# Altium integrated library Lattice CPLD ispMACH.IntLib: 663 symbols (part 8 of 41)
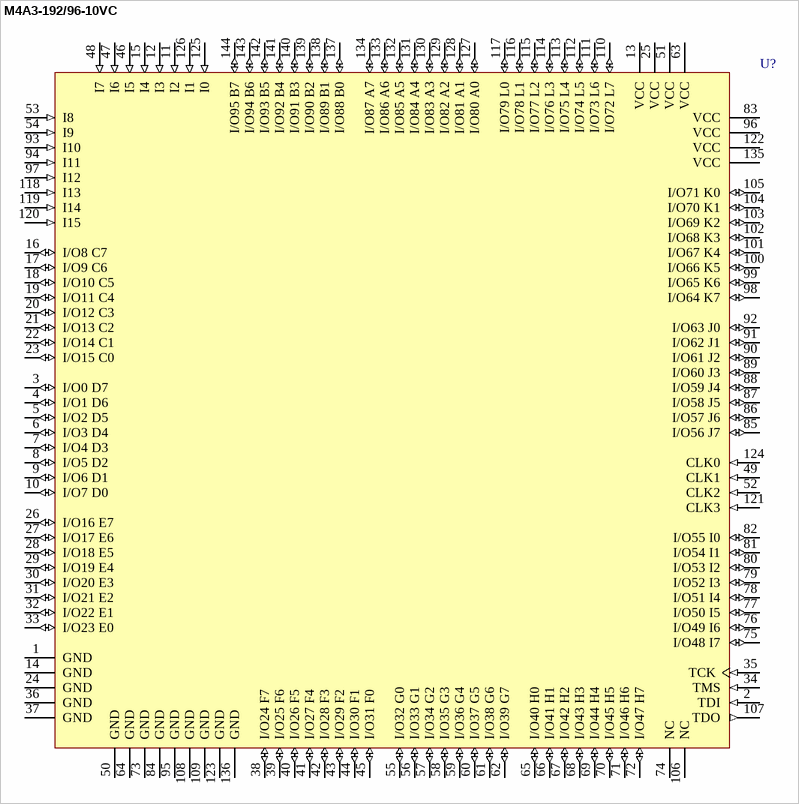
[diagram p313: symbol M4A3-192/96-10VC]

## M4A3-192/96-10VC
designator U?
High-Performance EE CMOS In-System Programmable Logic
footprint TQFP144_N (Thin QFP, 144-Leads, Body 20x20mm, Pitch 0.5mm, IPC Medium Density)
footprint TQFP144_L (Thin QFP, 144-Leads, Body 20x20mm, Pitch 0.5mm, IPC High Density)
footprint TQFP144_M (Thin QFP, 144-Leads, Body 20x20mm, Pitch 0.5mm, IPC Low Density)
3D model M4A3-TQFP144 (144-Pin Thin Quad Flat Pack (TQFP144))
pins: 1 GND (power), 2 TDI (in), 3 I/O0 D7 (io), 4 I/O1 D6 (io), 5 I/O2 D5 (io), 6 I/O3 D4 (io), 7 I/O4 D3 (io), 8 I/O5 D2 (io), 9 I/O6 D1 (io), 10 I/O7 D0 (io), 11 I2 (in), 12 I3 (in), 13 VCC (power), 14 GND (power), 15 I4 (in), 16 I/O8 C7 (io), 17 I/O9 C6 (io), 18 I/O10 C5 (io), 19 I/O11 C4 (io), 20 I/O12 C3 (io), 21 I/O13 C2 (io), 22 I/O14 C1 (io), 23 I/O15 C0 (io), 24 GND (power), 25 VCC (power), 26 I/O16 E7 (io), 27 I/O17 E6 (io), 28 I/O18 E5 (io), 29 I/O19 E4 (io), 30 I/O20 E3 (io), 31 I/O21 E2 (io), 32 I/O22 E1 (io), 33 I/O23 E0 (io), 34 TMS (in), 35 TCK (in), 36 GND (power), 37 GND (power), 38 I/O24 F7 (io), 39 I/O25 F6 (io), 40 I/O26 F5 (io), 41 I/O27 F4 (io), 42 I/O28 F3 (io), 43 I/O29 F2 (io), 44 I/O30 F1 (io), 45 I/O31 F0 (io), 46 I5 (in), 47 I6 (in), 48 I7 (in), 49 CLK1 (in), 50 GND (power), 51 VCC (power), 52 CLK2 (in), 53 I8 (in), 54 I9 (in), 55 I/O32 G0 (io), 56 I/O33 G1 (io), 57 I/O34 G2 (io), 58 I/O35 G3 (io), 59 I/O36 G4 (io), 60 I/O37 G5 (io), 61 I/O38 G6 (io), 62 I/O39 G7 (io), 63 VCC (power), 64 GND (power), 65 I/O40 H0 (io), 66 I/O41 H1 (io), 67 I/O42 H2 (io), 68 I/O43 H3 (io), 69 I/O44 H4 (io), 70 I/O45 H5 (io), 71 I/O46 H6 (io), 72 I/O47 H7 (io), 73 GND (power), 74 NC, 75 I/O48 I7 (io), 76 I/O49 I6 (io), 77 I/O50 I5 (io), 78 I/O51 I4 (io), 79 I/O52 I3 (io), 80 I/O53 I2 (io), 81 I/O54 I1 (io), 82 I/O55 I0 (io), 83 VCC (power), 84 GND (power), 85 I/O56 J7 (io), 86 I/O57 J6 (io), 87 I/O58 J5 (io), 88 I/O59 J4 (io), 89 I/O60 J3 (io), 90 I/O61 J2 (io), 91 I/O62 J1 (io), 92 I/O63 J0 (io), 93 I10 (in), 94 I11 (in), 95 GND (power), 96 VCC (power), 97 I12 (in), 98 I/O64 K7 (io), 99 I/O65 K6 (io), 100 I/O66 K5 (io), 101 I/O67 K4 (io), 102 I/O68 K3 (io), 103 I/O69 K2 (io), 104 I/O70 K1 (io), 105 I/O71 K0 (io), 106 NC, 107 TDO (out), 108 GND (power), 109 GND (power), 110 I/O72 L7 (io), 111 I/O73 L6 (io), 112 I/O74 L5 (io), 113 I/O75 L4 (io), 114 I/O76 L3 (io), 115 I/O77 L2 (io), 116 I/O78 L1 (io), 117 I/O79 L0 (io), 118 I13 (in), 119 I14 (in), 120 I15 (in), 121 CLK3 (in), 122 VCC (power), 123 GND (power), 124 CLK0 (in), 125 I0 (in), 126 I1 (in), 127 I/O80 A0 (io), 128 I/O81 A1 (io), 129 I/O82 A2 (io), 130 I/O83 A3 (io), 131 I/O84 A4 (io), 132 I/O85 A5 (io), 133 I/O86 A6 (io), 134 I/O87 A7 (io), 135 VCC (power), 136 GND (power), 137 I/O88 B0 (io), 138 I/O89 B1 (io), 139 I/O90 B2 (io), 140 I/O91 B3 (io), 141 I/O92 B4 (io), 142 I/O93 B5 (io), 143 I/O94 B6 (io), 144 I/O95 B7 (io)

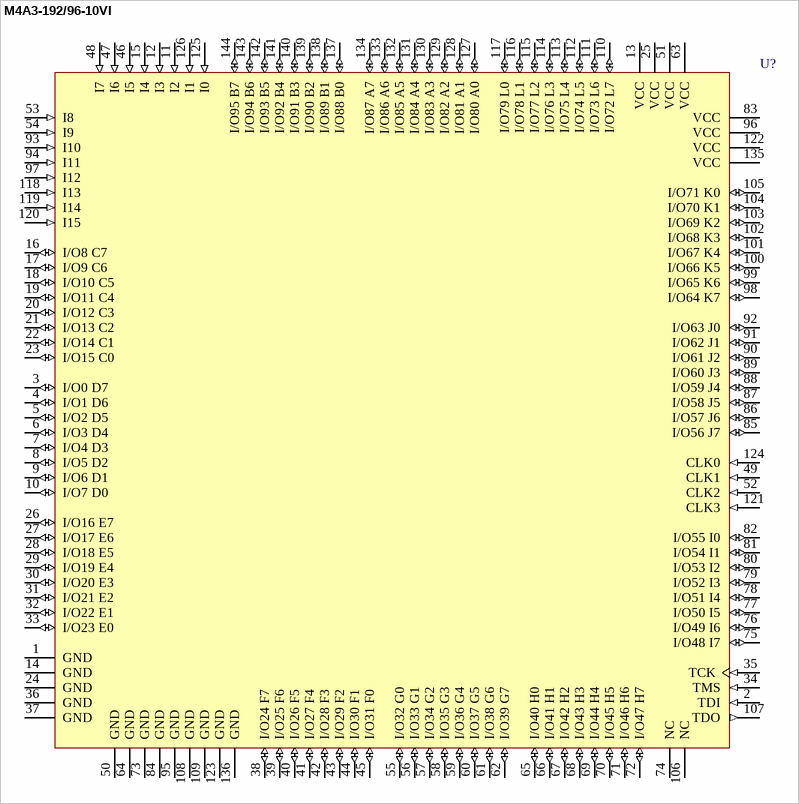
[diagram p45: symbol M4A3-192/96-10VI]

## M4A3-192/96-10VI
designator U?
High-Performance EE CMOS In-System Programmable Logic
footprint TQFP144_N (Thin QFP, 144-Leads, Body 20x20mm, Pitch 0.5mm, IPC Medium Density)
footprint TQFP144_L (Thin QFP, 144-Leads, Body 20x20mm, Pitch 0.5mm, IPC High Density)
footprint TQFP144_M (Thin QFP, 144-Leads, Body 20x20mm, Pitch 0.5mm, IPC Low Density)
3D model M4A3-TQFP144 (144-Pin Thin Quad Flat Pack (TQFP144))
pins: 1 GND (power), 2 TDI (in), 3 I/O0 D7 (io), 4 I/O1 D6 (io), 5 I/O2 D5 (io), 6 I/O3 D4 (io), 7 I/O4 D3 (io), 8 I/O5 D2 (io), 9 I/O6 D1 (io), 10 I/O7 D0 (io), 11 I2 (in), 12 I3 (in), 13 VCC (power), 14 GND (power), 15 I4 (in), 16 I/O8 C7 (io), 17 I/O9 C6 (io), 18 I/O10 C5 (io), 19 I/O11 C4 (io), 20 I/O12 C3 (io), 21 I/O13 C2 (io), 22 I/O14 C1 (io), 23 I/O15 C0 (io), 24 GND (power), 25 VCC (power), 26 I/O16 E7 (io), 27 I/O17 E6 (io), 28 I/O18 E5 (io), 29 I/O19 E4 (io), 30 I/O20 E3 (io), 31 I/O21 E2 (io), 32 I/O22 E1 (io), 33 I/O23 E0 (io), 34 TMS (in), 35 TCK (in), 36 GND (power), 37 GND (power), 38 I/O24 F7 (io), 39 I/O25 F6 (io), 40 I/O26 F5 (io), 41 I/O27 F4 (io), 42 I/O28 F3 (io), 43 I/O29 F2 (io), 44 I/O30 F1 (io), 45 I/O31 F0 (io), 46 I5 (in), 47 I6 (in), 48 I7 (in), 49 CLK1 (in), 50 GND (power), 51 VCC (power), 52 CLK2 (in), 53 I8 (in), 54 I9 (in), 55 I/O32 G0 (io), 56 I/O33 G1 (io), 57 I/O34 G2 (io), 58 I/O35 G3 (io), 59 I/O36 G4 (io), 60 I/O37 G5 (io), 61 I/O38 G6 (io), 62 I/O39 G7 (io), 63 VCC (power), 64 GND (power), 65 I/O40 H0 (io), 66 I/O41 H1 (io), 67 I/O42 H2 (io), 68 I/O43 H3 (io), 69 I/O44 H4 (io), 70 I/O45 H5 (io), 71 I/O46 H6 (io), 72 I/O47 H7 (io), 73 GND (power), 74 NC, 75 I/O48 I7 (io), 76 I/O49 I6 (io), 77 I/O50 I5 (io), 78 I/O51 I4 (io), 79 I/O52 I3 (io), 80 I/O53 I2 (io), 81 I/O54 I1 (io), 82 I/O55 I0 (io), 83 VCC (power), 84 GND (power), 85 I/O56 J7 (io), 86 I/O57 J6 (io), 87 I/O58 J5 (io), 88 I/O59 J4 (io), 89 I/O60 J3 (io), 90 I/O61 J2 (io), 91 I/O62 J1 (io), 92 I/O63 J0 (io), 93 I10 (in), 94 I11 (in), 95 GND (power), 96 VCC (power), 97 I12 (in), 98 I/O64 K7 (io), 99 I/O65 K6 (io), 100 I/O66 K5 (io), 101 I/O67 K4 (io), 102 I/O68 K3 (io), 103 I/O69 K2 (io), 104 I/O70 K1 (io), 105 I/O71 K0 (io), 106 NC, 107 TDO (out), 108 GND (power), 109 GND (power), 110 I/O72 L7 (io), 111 I/O73 L6 (io), 112 I/O74 L5 (io), 113 I/O75 L4 (io), 114 I/O76 L3 (io), 115 I/O77 L2 (io), 116 I/O78 L1 (io), 117 I/O79 L0 (io), 118 I13 (in), 119 I14 (in), 120 I15 (in), 121 CLK3 (in), 122 VCC (power), 123 GND (power), 124 CLK0 (in), 125 I0 (in), 126 I1 (in), 127 I/O80 A0 (io), 128 I/O81 A1 (io), 129 I/O82 A2 (io), 130 I/O83 A3 (io), 131 I/O84 A4 (io), 132 I/O85 A5 (io), 133 I/O86 A6 (io), 134 I/O87 A7 (io), 135 VCC (power), 136 GND (power), 137 I/O88 B0 (io), 138 I/O89 B1 (io), 139 I/O90 B2 (io), 140 I/O91 B3 (io), 141 I/O92 B4 (io), 142 I/O93 B5 (io), 143 I/O94 B6 (io), 144 I/O95 B7 (io)

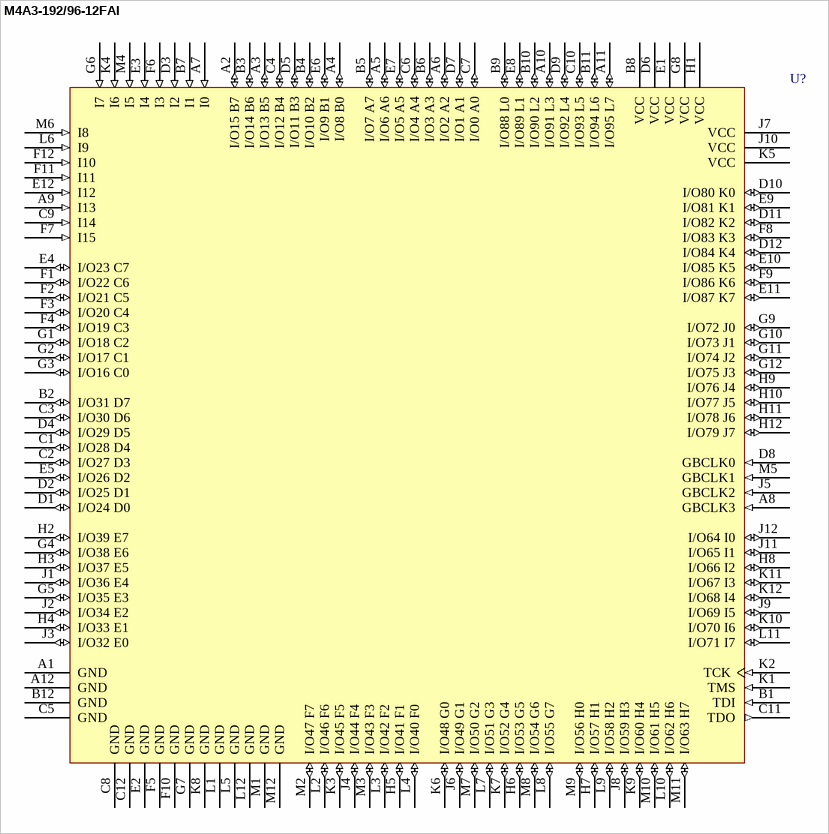
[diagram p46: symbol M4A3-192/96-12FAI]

## M4A3-192/96-12FAI
designator U?
High-Performance EE CMOS In-System Programmable Logic
footprint fpBGA144 (BGA, 144-Leads, Body 13x13mm, Pitch 1mm)
3D model M4A3-fpBGA144 (144-Ball Fine Pitch Ball Grid Array (fpBGA144))
pins: A1 GND (power), A2 I/O15 B7 (io), A3 I/O13 B5 (io), A4 I/O8 B0 (io), A5 I/O6 A6 (io), A6 I/O2 A2 (io), A7 I0 (in), A8 GBCLK3 (in), A9 I13 (in), A10 I/O91 L3 (io), A11 I/O95 L7 (io), A12 GND (power), B1 TDI (in), B2 I/O31 D7 (io), B3 I/O14 B6 (io), B4 I/O10 B2 (io), B5 I/O7 A7 (io), B6 I/O3 A3 (io), B7 I1 (in), B8 VCC (power), B9 I/O88 L0 (io), B10 I/O90 L2 (io), B11 I/O94 L6 (io), B12 GND (power), C1 I/O28 D4 (io), C2 I/O27 D3 (io), C3 I/O30 D6 (io), C4 I/O12 B4 (io), C5 GND (power), C6 I/O4 A4 (io), C7 I/O0 A0 (io), C8 GND (power), C9 I14 (in), C10 I/O93 L5 (io), C11 TDO (out), C12 GND (power), D1 I/O24 D0 (io), D2 I/O25 D1 (io), D3 I2 (in), D4 I/O29 D5 (io), D5 I/O11 B3 (io), D6 VCC (power), D7 I/O1 A1 (io), D8 GBCLK0 (in), D9 I/O92 L4 (io), D10 I/O80 K0 (io), D11 I/O82 K2 (io), D12 I/O84 K4 (io), E1 VCC (power), E2 GND (power), E3 I4 (in), E4 I/O23 C7 (io), E5 I/O26 D2 (io), E6 I/O9 B1 (io), E7 I/O5 A5 (io), E8 I/O89 L1 (io), E9 I/O81 K1 (io), E10 I/O85 K5 (io), E11 I/O87 K7 (io), E12 I12 (in), F1 I/O22 C6 (io), F2 I/O21 C5 (io), F3 I/O20 C4 (io), F4 I/O19 C3 (io), F5 GND (power), F6 I3 (in), F7 I15 (in), F8 I/O83 K3 (io), F9 I/O86 K6 (io), F10 GND (power), F11 I11 (in), F12 I10 (in), G1 I/O18 C2 (io), G2 I/O17 C1 (io), G3 I/O16 C0 (io), G4 I/O38 E6 (io), G5 I/O35 E3 (io), G6 I7 (in), G7 GND (power), G8 VCC (power), G9 I/O72 J0 (io), G10 I/O73 J1 (io), G11 I/O74 J2 (io), G12 I/O75 J3 (io), H1 VCC (power), H2 I/O39 E7 (io), H3 I/O37 E5 (io), H4 I/O33 E1 (io), H5 I/O41 F1 (io), H6 I/O53 G5 (io), H7 I/O57 H1 (io), H8 I/O66 I2 (io), H9 I/O76 J4 (io), H10 I/O77 J5 (io), H11 I/O78 J6 (io), H12 I/O79 J7 (io), J1 I/O36 E4 (io), J2 I/O34 E2 (io), J3 I/O32 E0 (io), J4 I/O44 F4 (io), J5 GBCLK2 (in), J6 I/O49 G1 (io), J7 VCC (power), J8 I/O59 H3 (io), J9 I/O69 I5 (io), J10 VCC (power), J11 I/O65 I1 (io), J12 I/O64 I0 (io), K1 TMS (in), K2 TCK (in), K3 I/O45 F5 (io), K4 I6 (in), K5 VCC (power), K6 I/O48 G0 (io), K7 I/O52 G4 (io), K8 GND (power), K9 I/O60 H4 (io), K10 I/O70 I6 (io), K11 I/O67 I3 (io), K12 I/O68 I4 (io), L1 GND (power), L2 I/O46 F6 (io), L3 I/O42 F2 (io), L4 I/O40 F0 (io), L5 GND (power), L6 I9 (in), L7 I/O51 G3 (io), L8 I/O55 G7 (io), L9 I/O58 H2 (io), L10 I/O62 H6 (io), L11 I/O71 I7 (io), L12 GND (power), M1 GND (power), M2 I/O47 F7 (io), M3 I/O43 F3 (io), M4 I5 (in), M5 GBCLK1 (in), M6 I8 (in), M7 I/O50 G2 (io), M8 I/O54 G6 (io), M9 I/O56 H0 (io), M10 I/O61 H5 (io), M11 I/O63 H7 (io), M12 GND (power)

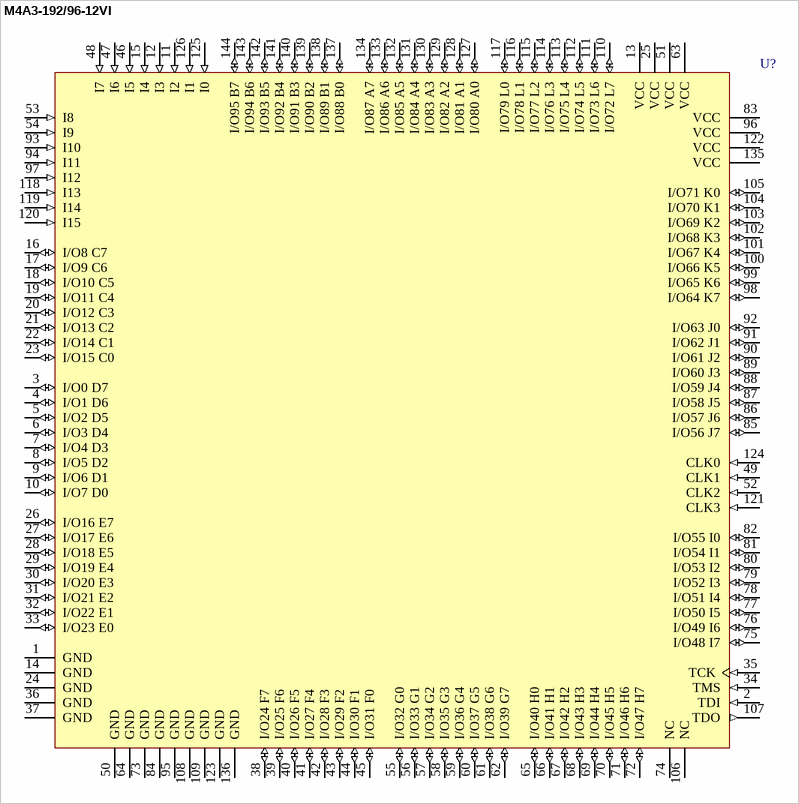
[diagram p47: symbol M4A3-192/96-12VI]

## M4A3-192/96-12VI
designator U?
High-Performance EE CMOS In-System Programmable Logic
footprint TQFP144_N (Thin QFP, 144-Leads, Body 20x20mm, Pitch 0.5mm, IPC Medium Density)
footprint TQFP144_L (Thin QFP, 144-Leads, Body 20x20mm, Pitch 0.5mm, IPC High Density)
footprint TQFP144_M (Thin QFP, 144-Leads, Body 20x20mm, Pitch 0.5mm, IPC Low Density)
3D model M4A3-TQFP144 (144-Pin Thin Quad Flat Pack (TQFP144))
pins: 1 GND (power), 2 TDI (in), 3 I/O0 D7 (io), 4 I/O1 D6 (io), 5 I/O2 D5 (io), 6 I/O3 D4 (io), 7 I/O4 D3 (io), 8 I/O5 D2 (io), 9 I/O6 D1 (io), 10 I/O7 D0 (io), 11 I2 (in), 12 I3 (in), 13 VCC (power), 14 GND (power), 15 I4 (in), 16 I/O8 C7 (io), 17 I/O9 C6 (io), 18 I/O10 C5 (io), 19 I/O11 C4 (io), 20 I/O12 C3 (io), 21 I/O13 C2 (io), 22 I/O14 C1 (io), 23 I/O15 C0 (io), 24 GND (power), 25 VCC (power), 26 I/O16 E7 (io), 27 I/O17 E6 (io), 28 I/O18 E5 (io), 29 I/O19 E4 (io), 30 I/O20 E3 (io), 31 I/O21 E2 (io), 32 I/O22 E1 (io), 33 I/O23 E0 (io), 34 TMS (in), 35 TCK (in), 36 GND (power), 37 GND (power), 38 I/O24 F7 (io), 39 I/O25 F6 (io), 40 I/O26 F5 (io), 41 I/O27 F4 (io), 42 I/O28 F3 (io), 43 I/O29 F2 (io), 44 I/O30 F1 (io), 45 I/O31 F0 (io), 46 I5 (in), 47 I6 (in), 48 I7 (in), 49 CLK1 (in), 50 GND (power), 51 VCC (power), 52 CLK2 (in), 53 I8 (in), 54 I9 (in), 55 I/O32 G0 (io), 56 I/O33 G1 (io), 57 I/O34 G2 (io), 58 I/O35 G3 (io), 59 I/O36 G4 (io), 60 I/O37 G5 (io), 61 I/O38 G6 (io), 62 I/O39 G7 (io), 63 VCC (power), 64 GND (power), 65 I/O40 H0 (io), 66 I/O41 H1 (io), 67 I/O42 H2 (io), 68 I/O43 H3 (io), 69 I/O44 H4 (io), 70 I/O45 H5 (io), 71 I/O46 H6 (io), 72 I/O47 H7 (io), 73 GND (power), 74 NC, 75 I/O48 I7 (io), 76 I/O49 I6 (io), 77 I/O50 I5 (io), 78 I/O51 I4 (io), 79 I/O52 I3 (io), 80 I/O53 I2 (io), 81 I/O54 I1 (io), 82 I/O55 I0 (io), 83 VCC (power), 84 GND (power), 85 I/O56 J7 (io), 86 I/O57 J6 (io), 87 I/O58 J5 (io), 88 I/O59 J4 (io), 89 I/O60 J3 (io), 90 I/O61 J2 (io), 91 I/O62 J1 (io), 92 I/O63 J0 (io), 93 I10 (in), 94 I11 (in), 95 GND (power), 96 VCC (power), 97 I12 (in), 98 I/O64 K7 (io), 99 I/O65 K6 (io), 100 I/O66 K5 (io), 101 I/O67 K4 (io), 102 I/O68 K3 (io), 103 I/O69 K2 (io), 104 I/O70 K1 (io), 105 I/O71 K0 (io), 106 NC, 107 TDO (out), 108 GND (power), 109 GND (power), 110 I/O72 L7 (io), 111 I/O73 L6 (io), 112 I/O74 L5 (io), 113 I/O75 L4 (io), 114 I/O76 L3 (io), 115 I/O77 L2 (io), 116 I/O78 L1 (io), 117 I/O79 L0 (io), 118 I13 (in), 119 I14 (in), 120 I15 (in), 121 CLK3 (in), 122 VCC (power), 123 GND (power), 124 CLK0 (in), 125 I0 (in), 126 I1 (in), 127 I/O80 A0 (io), 128 I/O81 A1 (io), 129 I/O82 A2 (io), 130 I/O83 A3 (io), 131 I/O84 A4 (io), 132 I/O85 A5 (io), 133 I/O86 A6 (io), 134 I/O87 A7 (io), 135 VCC (power), 136 GND (power), 137 I/O88 B0 (io), 138 I/O89 B1 (io), 139 I/O90 B2 (io), 140 I/O91 B3 (io), 141 I/O92 B4 (io), 142 I/O93 B5 (io), 143 I/O94 B6 (io), 144 I/O95 B7 (io)

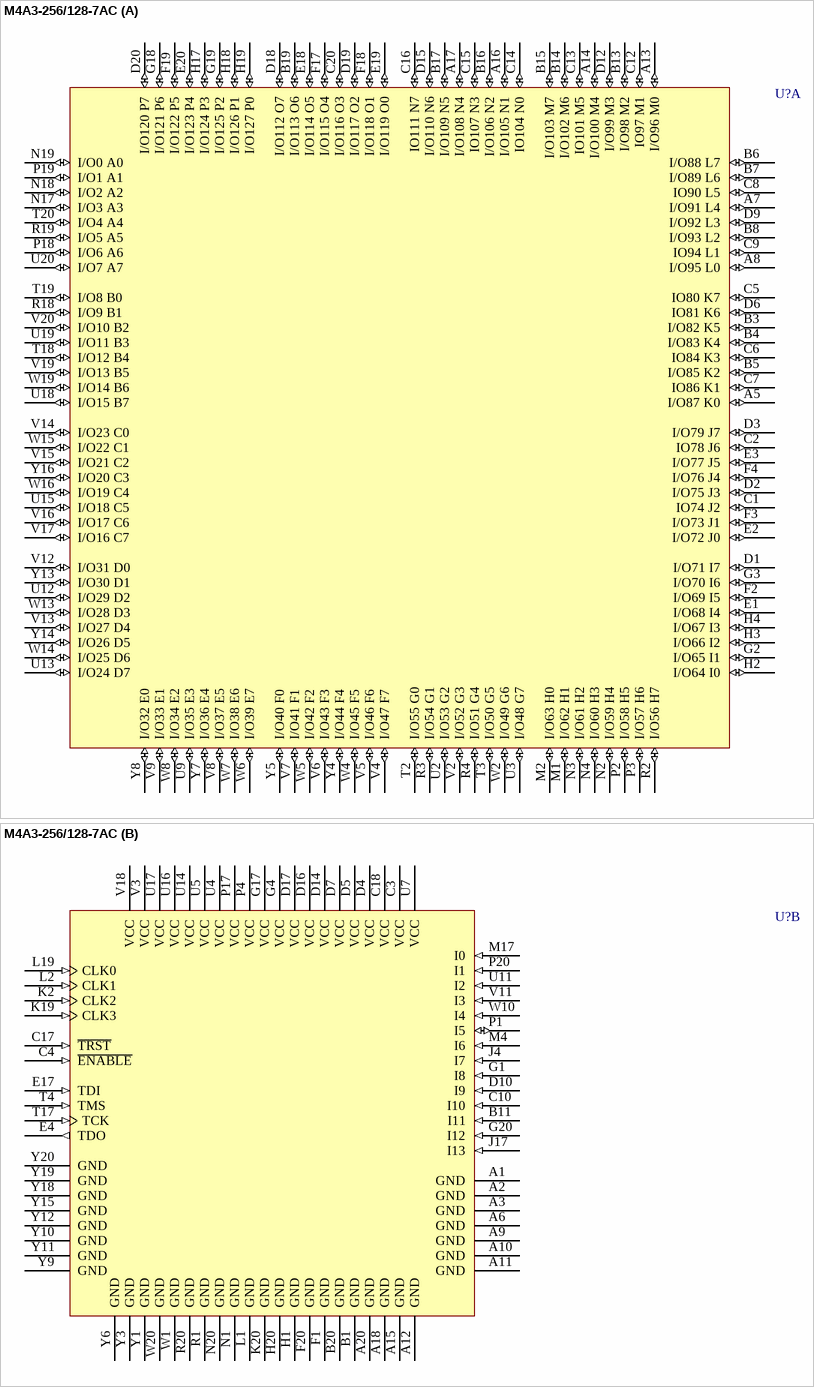
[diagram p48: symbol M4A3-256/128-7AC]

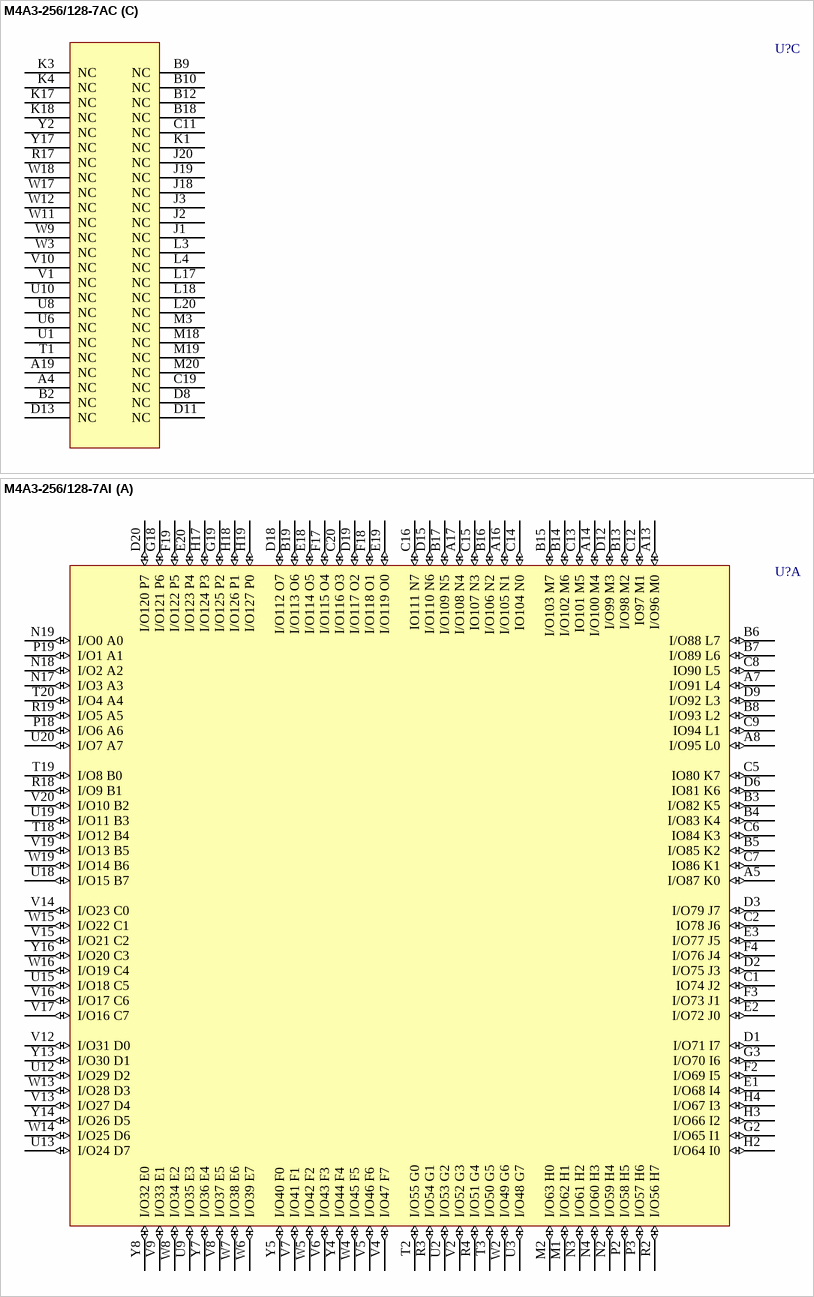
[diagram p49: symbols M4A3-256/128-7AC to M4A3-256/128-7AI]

## M4A3-256/128-7AC
designator U?
High-Performance EE CMOS In-System Programmable Logic
footprint SBGA256 (BGA, 256-Leads, Body 27x27mm, Pitch 1.27mm)
3D model M4A3-SBGA256 (256-Ball Super Ball Grid Array (SBGA256))
part A pins: A5 I/O87 K0 (io), A7 I/O91 L4 (io), A8 I/O95 L0 (io), A13 I/O96 M0 (io), A14 I/O100 M4 (io), A16 I/O105 N1 (io), A17 I/O108 N4 (io), B3 I/O82 K5 (io), B4 I/O83 K4 (io), B5 I/O85 K2 (io), B6 I/O88 L7 (io), B7 I/O89 L6 (io), B8 I/O93 L2 (io), B13 I/O98 M2 (io), B14 I/O102 M6 (io), B15 I/O103 M7 (io), B16 I/O106 N2 (io), B17 I/O109 N5 (io), B19 I/O113 O6 (io), C1 IO74 J2 (io), C2 IO78 J6 (io), C5 IO80 K7 (io), C6 IO84 K3 (io), C7 IO86 K1 (io), C8 IO90 L5 (io), C9 IO94 L1 (io), C12 IO97 M1 (io), C13 IO101 M5 (io), C14 IO104 N0 (io), C15 IO107 N3 (io), C16 IO111 N7 (io), C20 I/O116 O3 (io), D1 I/O71 I7 (io), D2 I/O75 J3 (io), D3 I/O79 J7 (io), D6 IO81 K6 (io), D9 I/O92 L3 (io), D12 I/O99 M3 (io), D15 I/O110 N6 (io), D18 I/O112 O7 (io), D19 I/O117 O2 (io), D20 I/O120 P7 (io), E1 I/O68 I4 (io), E2 I/O72 J0 (io), E3 I/O77 J5 (io), E18 I/O114 O5 (io), E19 I/O119 O0 (io), E20 I/O123 P4 (io), F2 I/O69 I5 (io), F3 I/O73 J1 (io), F4 I/O76 J4 (io), F17 I/O115 O4 (io), F18 I/O118 O1 (io), F19 I/O122 P5 (io), G2 I/O65 I1 (io), G3 I/O70 I6 (io), G18 I/O121 P6 (io), G19 I/O125 P2 (io), H2 I/O64 I0 (io), H3 I/O66 I2 (io), H4 I/O67 I3 (io), H17 I/O124 P3 (io), H18 I/O126 P1 (io), H19 I/O127 P0 (io), M1 I/O62 H1 (io), M2 I/O63 H0 (io), N2 I/O59 H4 (io), N3 I/O61 H2 (io), N4 I/O60 H3 (io), N17 I/O3 A3 (io), N18 I/O2 A2 (io), N19 I/O0 A0 (io), P2 I/O58 H5 (io), P3 I/O57 H6 (io), P18 I/O6 A6 (io), P19 I/O1 A1 (io), R2 I/O56 H7 (io), R3 I/O54 G1 (io), R4 I/O51 G4 (io), R18 I/O9 B1 (io), R19 I/O5 A5 (io), T2 I/O55 G0 (io), T3 I/O50 G5 (io), T18 I/O12 B4 (io), T19 I/O8 B0 (io), T20 I/O4 A4 (io), U2 I/O53 G2 (io), U3 I/O48 G7 (io), U9 I/O35 E3 (io), U12 I/O29 D2 (io), U13 I/O24 D7 (io), U15 I/O18 C5 (io), U18 I/O15 B7 (io), U19 I/O11 B3 (io), U20 I/O7 A7 (io), V2 I/O52 G3 (io), V4 I/O47 F7 (io), V5 I/O46 F6 (io), V6 I/O43 F3 (io), V7 I/O41 F1 (io), V8 I/O37 E5 (io), V9 I/O33 E1 (io), V12 I/O31 D0 (io), V13 I/O27 D4 (io), V14 I/O23 C0 (io), V15 I/O21 C2 (io), V16 I/O17 C6 (io), V17 I/O16 C7 (io), V19 I/O13 B5 (io), V20 I/O10 B2 (io), W2 I/O49 G6 (io), W4 I/O45 F5 (io), W5 I/O42 F2 (io), W6 I/O39 E7 (io), W7 I/O38 E6 (io), W8 I/O34 E2 (io), W13 I/O28 D3 (io), W14 I/O25 D6 (io), W15 I/O22 C1 (io), W16 I/O19 C4 (io), W19 I/O14 B6 (io), Y4 I/O44 F4 (io), Y5 I/O40 F0 (io), Y7 I/O36 E4 (io), Y8 I/O32 E0 (io), Y13 I/O30 D1 (io), Y14 I/O26 D5 (io), Y16 I/O20 C3 (io)
part B pins: A1 GND (power), A2 GND (power), A3 GND (power), A6 GND (power), A9 GND (power), A10 GND (power), A11 GND (power), A12 GND (power), A15 GND (power), A18 GND (power), A20 GND (power), B1 GND (power), B11 I11 (in), B20 GND (power), C3 VCC (power), C4 ~{ENABLE} (in), C10 I10 (in), C17 ~{TRST} (in), C18 VCC (power), D4 VCC (power), D5 VCC (power), D7 VCC (power), D10 I9 (in), D14 VCC (power), D16 VCC (power), D17 VCC (power), E4 TDO (out), E17 TDI (in), F1 GND (power), F20 GND (power), G1 I8 (in), G4 VCC (power), G17 VCC (power), G20 I12 (in), H1 GND (power), H20 GND (power), J4 I7 (in), J17 I13 (in), K2 CLK2 (in), K19 CLK3 (in), K20 GND (power), L1 GND (power), L2 CLK1 (in), L19 CLK0 (in), M4 I6 (in), M17 I0 (in), N1 GND (power), N20 GND (power), P1 I5 (io), P4 VCC (power), P17 VCC (power), P20 I1 (in), R1 GND (power), R20 GND (power), T4 TMS (in), T17 TCK (in), U4 VCC (power), U5 VCC (power), U7 VCC (power), U11 I2 (in), U14 VCC (power), U16 VCC (power), U17 VCC (power), V3 VCC (power), V11 I3 (in), V18 VCC (power), W1 GND (power), W10 I4 (in), W20 GND (power), Y1 GND (power), Y3 GND (power), Y6 GND (power), Y9 GND (power), Y10 GND (power), Y11 GND (power), Y12 GND (power), Y15 GND (power), Y18 GND (power), Y19 GND (power), Y20 GND (power)
part C pins: A4 NC, A19 NC, B2 NC, B9 NC, B10 NC, B12 NC, B18 NC, C11 NC, C19 NC, D8 NC, D11 NC, D13 NC, J1 NC, J2 NC, J3 NC, J18 NC, J19 NC, J20 NC, K1 NC, K3 NC, K4 NC, K17 NC, K18 NC, L3 NC, L4 NC, L17 NC, L18 NC, L20 NC, M3 NC, M18 NC, M19 NC, M20 NC, R17 NC, T1 NC, U1 NC, U6 NC, U8 NC, U10 NC, V1 NC, V10 NC, W3 NC, W9 NC, W11 NC, W12 NC, W17 NC, W18 NC, Y2 NC, Y17 NC

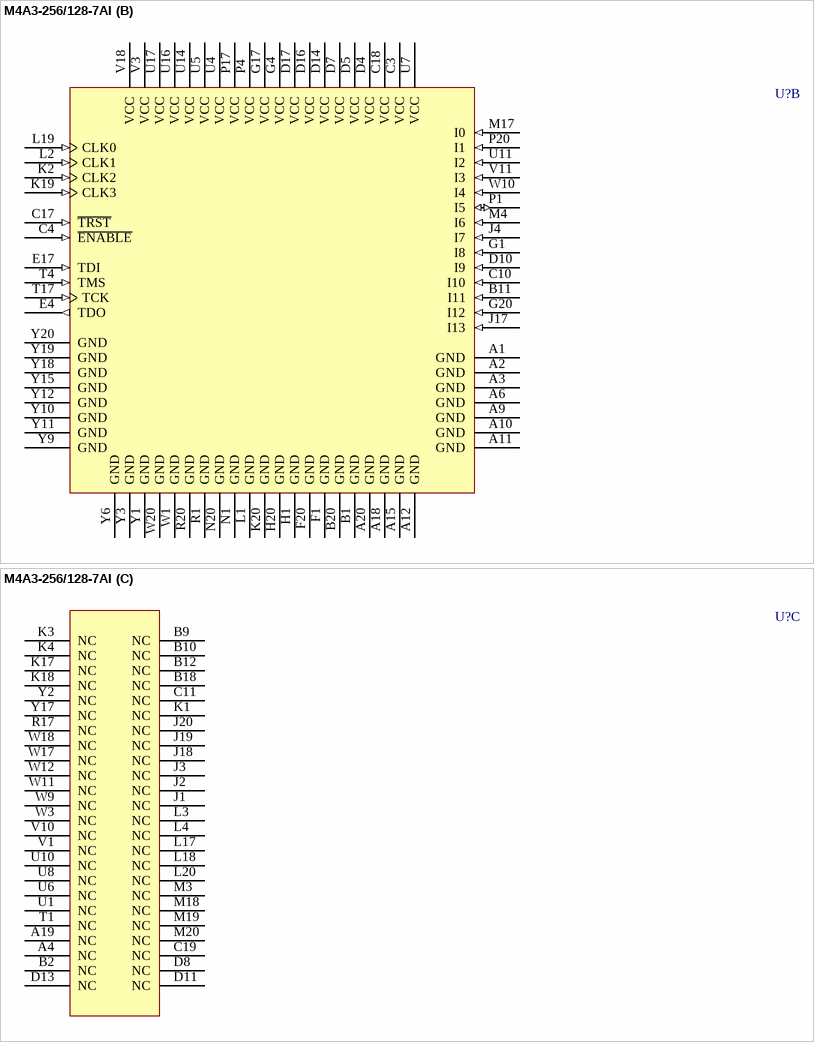
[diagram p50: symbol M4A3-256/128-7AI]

## M4A3-256/128-7AI
designator U?
High-Performance EE CMOS In-System Programmable Logic
footprint SBGA256 (BGA, 256-Leads, Body 27x27mm, Pitch 1.27mm)
3D model M4A3-SBGA256 (256-Ball Super Ball Grid Array (SBGA256))
part A pins: A5 I/O87 K0 (io), A7 I/O91 L4 (io), A8 I/O95 L0 (io), A13 I/O96 M0 (io), A14 I/O100 M4 (io), A16 I/O105 N1 (io), A17 I/O108 N4 (io), B3 I/O82 K5 (io), B4 I/O83 K4 (io), B5 I/O85 K2 (io), B6 I/O88 L7 (io), B7 I/O89 L6 (io), B8 I/O93 L2 (io), B13 I/O98 M2 (io), B14 I/O102 M6 (io), B15 I/O103 M7 (io), B16 I/O106 N2 (io), B17 I/O109 N5 (io), B19 I/O113 O6 (io), C1 IO74 J2 (io), C2 IO78 J6 (io), C5 IO80 K7 (io), C6 IO84 K3 (io), C7 IO86 K1 (io), C8 IO90 L5 (io), C9 IO94 L1 (io), C12 IO97 M1 (io), C13 IO101 M5 (io), C14 IO104 N0 (io), C15 IO107 N3 (io), C16 IO111 N7 (io), C20 I/O116 O3 (io), D1 I/O71 I7 (io), D2 I/O75 J3 (io), D3 I/O79 J7 (io), D6 IO81 K6 (io), D9 I/O92 L3 (io), D12 I/O99 M3 (io), D15 I/O110 N6 (io), D18 I/O112 O7 (io), D19 I/O117 O2 (io), D20 I/O120 P7 (io), E1 I/O68 I4 (io), E2 I/O72 J0 (io), E3 I/O77 J5 (io), E18 I/O114 O5 (io), E19 I/O119 O0 (io), E20 I/O123 P4 (io), F2 I/O69 I5 (io), F3 I/O73 J1 (io), F4 I/O76 J4 (io), F17 I/O115 O4 (io), F18 I/O118 O1 (io), F19 I/O122 P5 (io), G2 I/O65 I1 (io), G3 I/O70 I6 (io), G18 I/O121 P6 (io), G19 I/O125 P2 (io), H2 I/O64 I0 (io), H3 I/O66 I2 (io), H4 I/O67 I3 (io), H17 I/O124 P3 (io), H18 I/O126 P1 (io), H19 I/O127 P0 (io), M1 I/O62 H1 (io), M2 I/O63 H0 (io), N2 I/O59 H4 (io), N3 I/O61 H2 (io), N4 I/O60 H3 (io), N17 I/O3 A3 (io), N18 I/O2 A2 (io), N19 I/O0 A0 (io), P2 I/O58 H5 (io), P3 I/O57 H6 (io), P18 I/O6 A6 (io), P19 I/O1 A1 (io), R2 I/O56 H7 (io), R3 I/O54 G1 (io), R4 I/O51 G4 (io), R18 I/O9 B1 (io), R19 I/O5 A5 (io), T2 I/O55 G0 (io), T3 I/O50 G5 (io), T18 I/O12 B4 (io), T19 I/O8 B0 (io), T20 I/O4 A4 (io), U2 I/O53 G2 (io), U3 I/O48 G7 (io), U9 I/O35 E3 (io), U12 I/O29 D2 (io), U13 I/O24 D7 (io), U15 I/O18 C5 (io), U18 I/O15 B7 (io), U19 I/O11 B3 (io), U20 I/O7 A7 (io), V2 I/O52 G3 (io), V4 I/O47 F7 (io), V5 I/O46 F6 (io), V6 I/O43 F3 (io), V7 I/O41 F1 (io), V8 I/O37 E5 (io), V9 I/O33 E1 (io), V12 I/O31 D0 (io), V13 I/O27 D4 (io), V14 I/O23 C0 (io), V15 I/O21 C2 (io), V16 I/O17 C6 (io), V17 I/O16 C7 (io), V19 I/O13 B5 (io), V20 I/O10 B2 (io), W2 I/O49 G6 (io), W4 I/O45 F5 (io), W5 I/O42 F2 (io), W6 I/O39 E7 (io), W7 I/O38 E6 (io), W8 I/O34 E2 (io), W13 I/O28 D3 (io), W14 I/O25 D6 (io), W15 I/O22 C1 (io), W16 I/O19 C4 (io), W19 I/O14 B6 (io), Y4 I/O44 F4 (io), Y5 I/O40 F0 (io), Y7 I/O36 E4 (io), Y8 I/O32 E0 (io), Y13 I/O30 D1 (io), Y14 I/O26 D5 (io), Y16 I/O20 C3 (io)
part B pins: A1 GND (power), A2 GND (power), A3 GND (power), A6 GND (power), A9 GND (power), A10 GND (power), A11 GND (power), A12 GND (power), A15 GND (power), A18 GND (power), A20 GND (power), B1 GND (power), B11 I11 (in), B20 GND (power), C3 VCC (power), C4 ~{ENABLE} (in), C10 I10 (in), C17 ~{TRST} (in), C18 VCC (power), D4 VCC (power), D5 VCC (power), D7 VCC (power), D10 I9 (in), D14 VCC (power), D16 VCC (power), D17 VCC (power), E4 TDO (out), E17 TDI (in), F1 GND (power), F20 GND (power), G1 I8 (in), G4 VCC (power), G17 VCC (power), G20 I12 (in), H1 GND (power), H20 GND (power), J4 I7 (in), J17 I13 (in), K2 CLK2 (in), K19 CLK3 (in), K20 GND (power), L1 GND (power), L2 CLK1 (in), L19 CLK0 (in), M4 I6 (in), M17 I0 (in), N1 GND (power), N20 GND (power), P1 I5 (io), P4 VCC (power), P17 VCC (power), P20 I1 (in), R1 GND (power), R20 GND (power), T4 TMS (in), T17 TCK (in), U4 VCC (power), U5 VCC (power), U7 VCC (power), U11 I2 (in), U14 VCC (power), U16 VCC (power), U17 VCC (power), V3 VCC (power), V11 I3 (in), V18 VCC (power), W1 GND (power), W10 I4 (in), W20 GND (power), Y1 GND (power), Y3 GND (power), Y6 GND (power), Y9 GND (power), Y10 GND (power), Y11 GND (power), Y12 GND (power), Y15 GND (power), Y18 GND (power), Y19 GND (power), Y20 GND (power)
part C pins: A4 NC, A19 NC, B2 NC, B9 NC, B10 NC, B12 NC, B18 NC, C11 NC, C19 NC, D8 NC, D11 NC, D13 NC, J1 NC, J2 NC, J3 NC, J18 NC, J19 NC, J20 NC, K1 NC, K3 NC, K4 NC, K17 NC, K18 NC, L3 NC, L4 NC, L17 NC, L18 NC, L20 NC, M3 NC, M18 NC, M19 NC, M20 NC, R17 NC, T1 NC, U1 NC, U6 NC, U8 NC, U10 NC, V1 NC, V10 NC, W3 NC, W9 NC, W11 NC, W12 NC, W17 NC, W18 NC, Y2 NC, Y17 NC

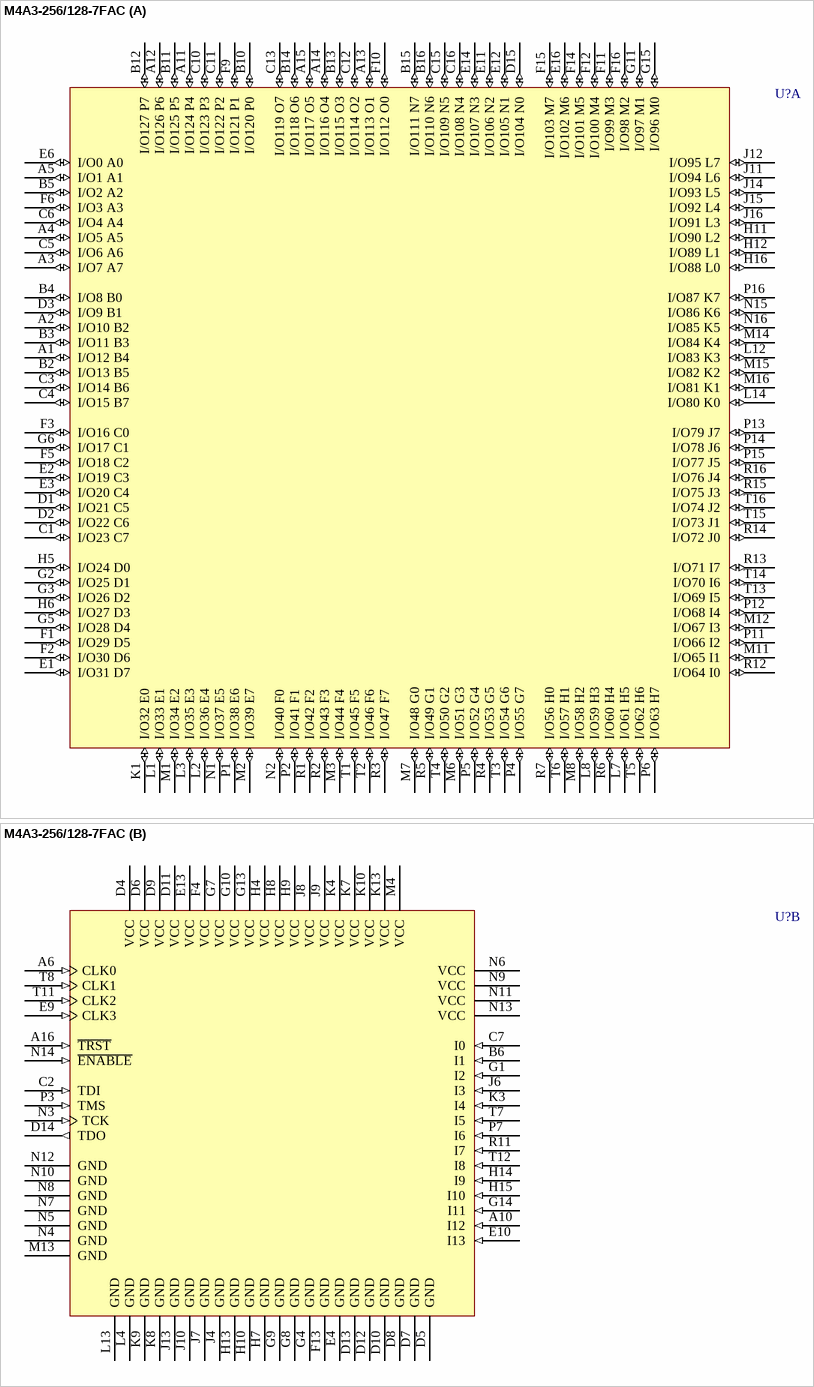
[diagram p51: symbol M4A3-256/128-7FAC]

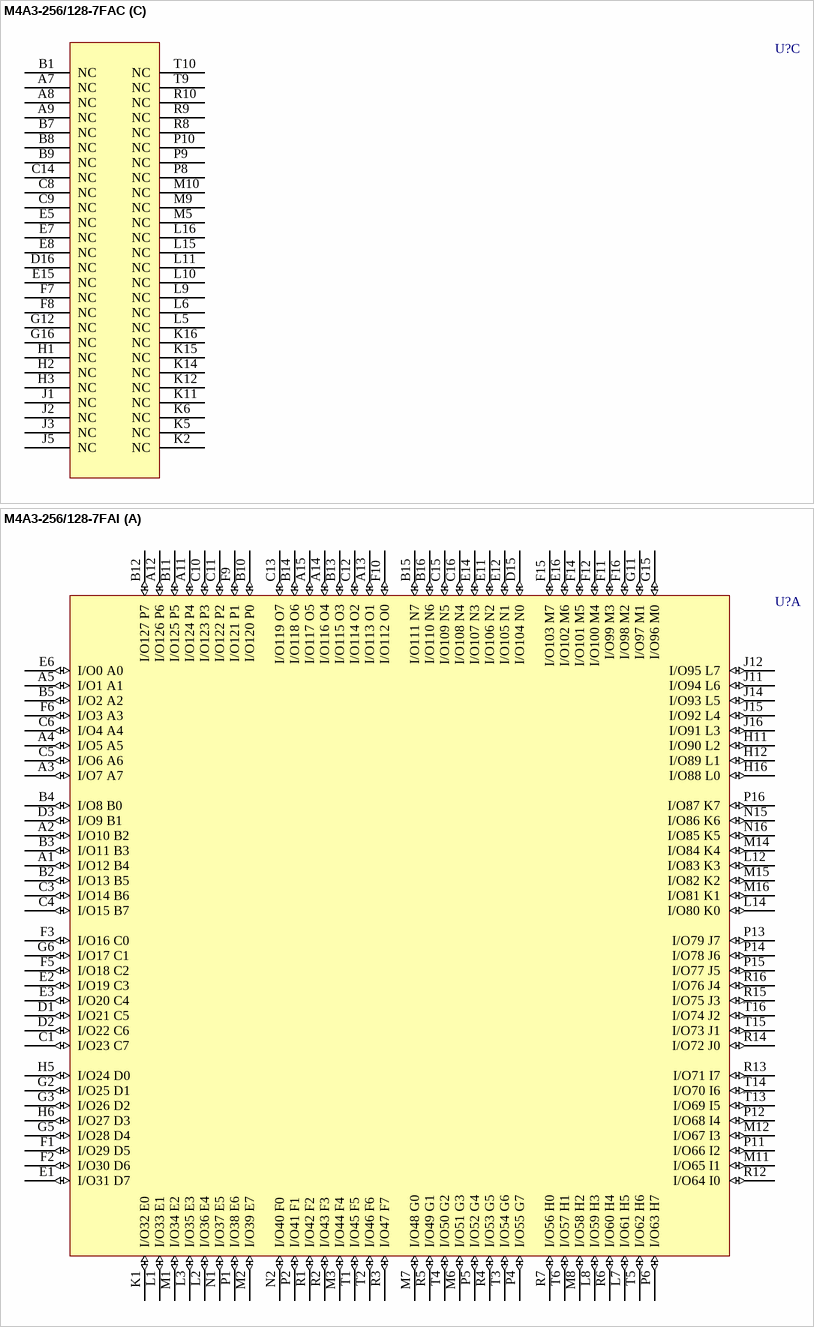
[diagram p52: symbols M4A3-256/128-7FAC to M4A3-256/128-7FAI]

## M4A3-256/128-7FAC
designator U?
High-Performance EE CMOS In-System Programmable Logic
footprint fpBGA256 (BGA, 256-Leads, Body 17x17mm, Pitch 1mm)
3D model M4A3-fpBGA256 (256-Ball Fine Pitch Ball Grid Array (fpBGA256))
part A pins: A1 I/O12 B4 (io), A2 I/O10 B2 (io), A3 I/O7 A7 (io), A4 I/O5 A5 (io), A5 I/O1 A1 (io), A11 I/O124 P4 (io), A12 I/O126 P6 (io), A13 I/O113 O1 (io), A14 I/O116 O4 (io), A15 I/O117 O5 (io), B2 I/O13 B5 (io), B3 I/O11 B3 (io), B4 I/O8 B0 (io), B5 I/O2 A2 (io), B10 I/O120 P0 (io), B11 I/O125 P5 (io), B12 I/O127 P7 (io), B13 I/O115 O3 (io), B14 I/O118 O6 (io), B15 I/O111 N7 (io), B16 I/O110 N6 (io), C1 I/O23 C7 (io), C3 I/O14 B6 (io), C4 I/O15 B7 (io), C5 I/O6 A6 (io), C6 I/O4 A4 (io), C10 I/O123 P3 (io), C11 I/O122 P2 (io), C12 I/O114 O2 (io), C13 I/O119 O7 (io), C15 I/O109 N5 (io), C16 I/O108 N4 (io), D1 I/O21 C5 (io), D2 I/O22 C6 (io), D3 I/O9 B1 (io), D15 I/O104 N0 (io), E1 I/O31 D7 (io), E2 I/O19 C3 (io), E3 I/O20 C4 (io), E6 I/O0 A0 (io), E11 I/O106 N2 (io), E12 I/O105 N1 (io), E14 I/O107 N3 (io), E16 I/O102 M6 (io), F1 I/O29 D5 (io), F2 I/O30 D6 (io), F3 I/O16 C0 (io), F5 I/O18 C2 (io), F6 I/O3 A3 (io), F9 I/O121 P1 (io), F10 I/O112 O0 (io), F11 I/O99 M3 (io), F12 I/O100 M4 (io), F14 I/O101 M5 (io), F15 I/O103 M7 (io), F16 I/O98 M2 (io), G2 I/O25 D1 (io), G3 I/O26 D2 (io), G5 I/O28 D4 (io), G6 I/O17 C1 (io), G11 I/O97 M1 (io), G15 I/O96 M0 (io), H5 I/O24 D0 (io), H6 I/O27 D3 (io), H11 I/O90 L2 (io), H12 I/O89 L1 (io), H16 I/O88 L0 (io), J11 I/O94 L6 (io), J12 I/O95 L7 (io), J14 I/O93 L5 (io), J15 I/O92 L4 (io), J16 I/O91 L3 (io), K1 I/O32 E0 (io), L1 I/O33 E1 (io), L2 I/O36 E4 (io), L3 I/O35 E3 (io), L7 I/O61 H5 (io), L8 I/O59 H3 (io), L12 I/O83 K3 (io), L14 I/O80 K0 (io), M1 I/O34 E2 (io), M2 I/O39 E7 (io), M3 I/O44 F4 (io), M6 I/O51 G3 (io), M7 I/O48 G0 (io), M8 I/O58 H2 (io), M11 I/O65 I1 (io), M12 I/O67 I3 (io), M14 I/O84 K4 (io), M15 I/O82 K2 (io), M16 I/O81 K1 (io), N1 I/O37 E5 (io), N2 I/O40 F0 (io), N15 I/O86 K6 (io), N16 I/O85 K5 (io), P1 I/O38 E6 (io), P2 I/O41 F1 (io), P4 I/O55 G7 (io), P5 I/O52 G4 (io), P6 I/O63 H7 (io), P11 I/O66 I2 (io), P12 I/O68 I4 (io), P13 I/O79 J7 (io), P14 I/O78 J6 (io), P15 I/O77 J5 (io), P16 I/O87 K7 (io), R1 I/O42 F2 (io), R2 I/O43 F3 (io), R3 I/O47 F7 (io), R4 I/O53 G5 (io), R5 I/O49 G1 (io), R6 I/O60 H4 (io), R7 I/O56 H0 (io), R12 I/O64 I0 (io), R13 I/O71 I7 (io), R14 I/O72 J0 (io), R15 I/O75 J3 (io), R16 I/O76 J4 (io), T1 I/O45 F5 (io), T2 I/O46 F6 (io), T3 I/O54 G6 (io), T4 I/O50 G2 (io), T5 I/O62 H6 (io), T6 I/O57 H1 (io), T13 I/O69 I5 (io), T14 I/O70 I6 (io), T15 I/O73 J1 (io), T16 I/O74 J2 (io)
part B pins: A6 CLK0 (in), A10 I12 (in), A16 ~{TRST} (in), B6 I1 (in), C2 TDI (in), C7 I0 (in), D4 VCC (power), D5 GND (power), D6 VCC (power), D7 GND (power), D8 GND (power), D9 VCC (power), D10 GND (power), D11 VCC (power), D12 GND (power), D13 GND (power), D14 TDO (out), E4 GND (power), E9 CLK3 (in), E10 I13 (in), E13 VCC (power), F4 VCC (power), F13 GND (power), G1 I2 (in), G4 GND (power), G7 VCC (power), G8 GND (power), G9 GND (power), G10 VCC (power), G13 VCC (power), G14 I11 (in), H4 VCC (power), H7 GND (power), H8 VCC (power), H9 VCC (power), H10 GND (power), H13 GND (power), H14 I9 (in), H15 I10 (in), J4 GND (power), J6 I3 (in), J7 GND (power), J8 VCC (power), J9 VCC (power), J10 GND (power), J13 GND (power), K3 I4 (in), K4 VCC (power), K7 VCC (power), K8 GND (power), K9 GND (power), K10 VCC (power), K13 VCC (power), L4 GND (power), L13 GND (power), M4 VCC (power), M13 GND (power), N3 TCK (in), N4 GND (power), N5 GND (power), N6 VCC (power), N7 GND (power), N8 GND (power), N9 VCC (power), N10 GND (power), N11 VCC (power), N12 GND (power), N13 VCC (power), N14 ~{ENABLE} (in), P3 TMS (in), P7 I6 (in), R11 I7 (in), T7 I5 (in), T8 CLK1 (in), T11 CLK2 (in), T12 I8 (in)
part C pins: A7 NC, A8 NC, A9 NC, B1 NC, B7 NC, B8 NC, B9 NC, C8 NC, C9 NC, C14 NC, D16 NC, E5 NC, E7 NC, E8 NC, E15 NC, F7 NC, F8 NC, G12 NC, G16 NC, H1 NC, H2 NC, H3 NC, J1 NC, J2 NC, J3 NC, J5 NC, K2 NC, K5 NC, K6 NC, K11 NC, K12 NC, K14 NC, K15 NC, K16 NC, L5 NC, L6 NC, L9 NC, L10 NC, L11 NC, L15 NC, L16 NC, M5 NC, M9 NC, M10 NC, P8 NC, P9 NC, P10 NC, R8 NC, R9 NC, R10 NC, T9 NC, T10 NC

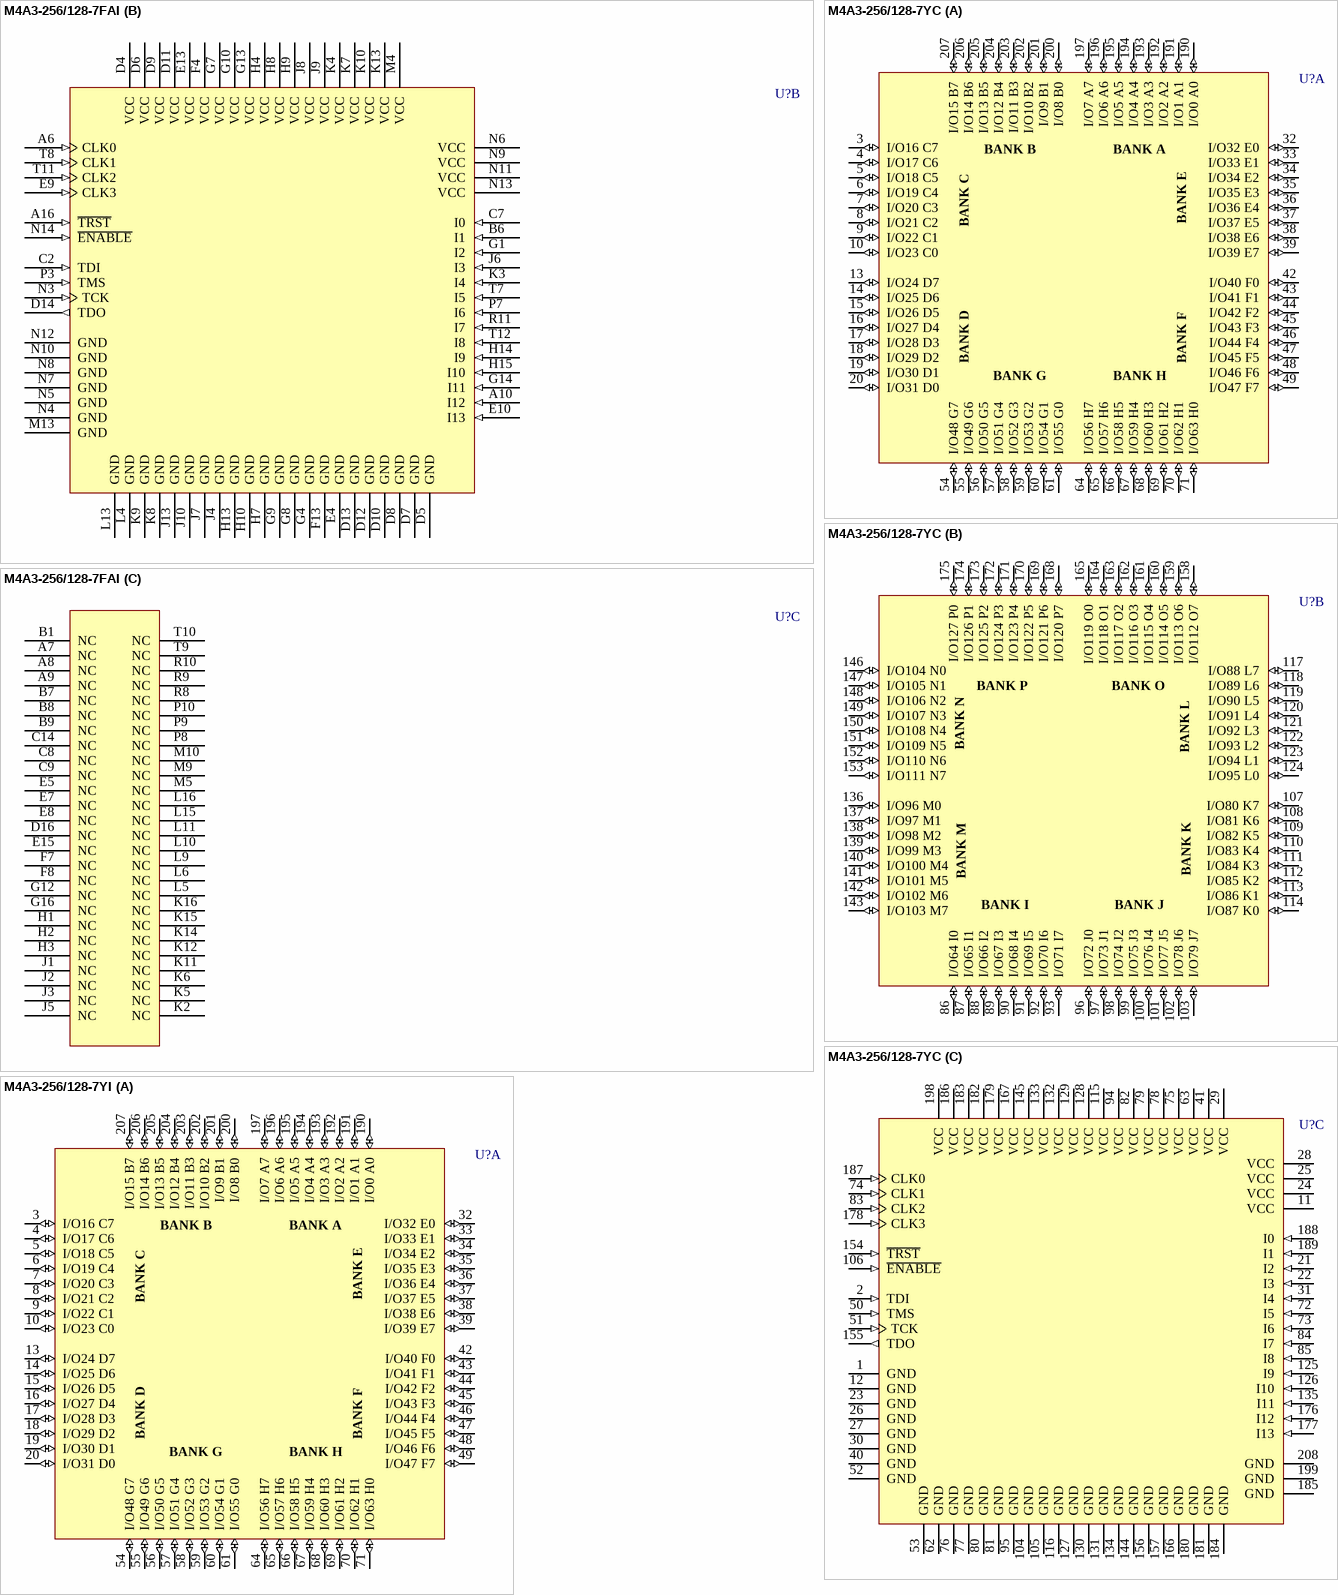
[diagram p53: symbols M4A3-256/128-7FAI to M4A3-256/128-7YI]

## M4A3-256/128-7FAI
designator U?
High-Performance EE CMOS In-System Programmable Logic
footprint fpBGA256 (BGA, 256-Leads, Body 17x17mm, Pitch 1mm)
3D model M4A3-fpBGA256 (256-Ball Fine Pitch Ball Grid Array (fpBGA256))
part A pins: A1 I/O12 B4 (io), A2 I/O10 B2 (io), A3 I/O7 A7 (io), A4 I/O5 A5 (io), A5 I/O1 A1 (io), A11 I/O124 P4 (io), A12 I/O126 P6 (io), A13 I/O113 O1 (io), A14 I/O116 O4 (io), A15 I/O117 O5 (io), B2 I/O13 B5 (io), B3 I/O11 B3 (io), B4 I/O8 B0 (io), B5 I/O2 A2 (io), B10 I/O120 P0 (io), B11 I/O125 P5 (io), B12 I/O127 P7 (io), B13 I/O115 O3 (io), B14 I/O118 O6 (io), B15 I/O111 N7 (io), B16 I/O110 N6 (io), C1 I/O23 C7 (io), C3 I/O14 B6 (io), C4 I/O15 B7 (io), C5 I/O6 A6 (io), C6 I/O4 A4 (io), C10 I/O123 P3 (io), C11 I/O122 P2 (io), C12 I/O114 O2 (io), C13 I/O119 O7 (io), C15 I/O109 N5 (io), C16 I/O108 N4 (io), D1 I/O21 C5 (io), D2 I/O22 C6 (io), D3 I/O9 B1 (io), D15 I/O104 N0 (io), E1 I/O31 D7 (io), E2 I/O19 C3 (io), E3 I/O20 C4 (io), E6 I/O0 A0 (io), E11 I/O106 N2 (io), E12 I/O105 N1 (io), E14 I/O107 N3 (io), E16 I/O102 M6 (io), F1 I/O29 D5 (io), F2 I/O30 D6 (io), F3 I/O16 C0 (io), F5 I/O18 C2 (io), F6 I/O3 A3 (io), F9 I/O121 P1 (io), F10 I/O112 O0 (io), F11 I/O99 M3 (io), F12 I/O100 M4 (io), F14 I/O101 M5 (io), F15 I/O103 M7 (io), F16 I/O98 M2 (io), G2 I/O25 D1 (io), G3 I/O26 D2 (io), G5 I/O28 D4 (io), G6 I/O17 C1 (io), G11 I/O97 M1 (io), G15 I/O96 M0 (io), H5 I/O24 D0 (io), H6 I/O27 D3 (io), H11 I/O90 L2 (io), H12 I/O89 L1 (io), H16 I/O88 L0 (io), J11 I/O94 L6 (io), J12 I/O95 L7 (io), J14 I/O93 L5 (io), J15 I/O92 L4 (io), J16 I/O91 L3 (io), K1 I/O32 E0 (io), L1 I/O33 E1 (io), L2 I/O36 E4 (io), L3 I/O35 E3 (io), L7 I/O61 H5 (io), L8 I/O59 H3 (io), L12 I/O83 K3 (io), L14 I/O80 K0 (io), M1 I/O34 E2 (io), M2 I/O39 E7 (io), M3 I/O44 F4 (io), M6 I/O51 G3 (io), M7 I/O48 G0 (io), M8 I/O58 H2 (io), M11 I/O65 I1 (io), M12 I/O67 I3 (io), M14 I/O84 K4 (io), M15 I/O82 K2 (io), M16 I/O81 K1 (io), N1 I/O37 E5 (io), N2 I/O40 F0 (io), N15 I/O86 K6 (io), N16 I/O85 K5 (io), P1 I/O38 E6 (io), P2 I/O41 F1 (io), P4 I/O55 G7 (io), P5 I/O52 G4 (io), P6 I/O63 H7 (io), P11 I/O66 I2 (io), P12 I/O68 I4 (io), P13 I/O79 J7 (io), P14 I/O78 J6 (io), P15 I/O77 J5 (io), P16 I/O87 K7 (io), R1 I/O42 F2 (io), R2 I/O43 F3 (io), R3 I/O47 F7 (io), R4 I/O53 G5 (io), R5 I/O49 G1 (io), R6 I/O60 H4 (io), R7 I/O56 H0 (io), R12 I/O64 I0 (io), R13 I/O71 I7 (io), R14 I/O72 J0 (io), R15 I/O75 J3 (io), R16 I/O76 J4 (io), T1 I/O45 F5 (io), T2 I/O46 F6 (io), T3 I/O54 G6 (io), T4 I/O50 G2 (io), T5 I/O62 H6 (io), T6 I/O57 H1 (io), T13 I/O69 I5 (io), T14 I/O70 I6 (io), T15 I/O73 J1 (io), T16 I/O74 J2 (io)
part B pins: A6 CLK0 (in), A10 I12 (in), A16 ~{TRST} (in), B6 I1 (in), C2 TDI (in), C7 I0 (in), D4 VCC (power), D5 GND (power), D6 VCC (power), D7 GND (power), D8 GND (power), D9 VCC (power), D10 GND (power), D11 VCC (power), D12 GND (power), D13 GND (power), D14 TDO (out), E4 GND (power), E9 CLK3 (in), E10 I13 (in), E13 VCC (power), F4 VCC (power), F13 GND (power), G1 I2 (in), G4 GND (power), G7 VCC (power), G8 GND (power), G9 GND (power), G10 VCC (power), G13 VCC (power), G14 I11 (in), H4 VCC (power), H7 GND (power), H8 VCC (power), H9 VCC (power), H10 GND (power), H13 GND (power), H14 I9 (in), H15 I10 (in), J4 GND (power), J6 I3 (in), J7 GND (power), J8 VCC (power), J9 VCC (power), J10 GND (power), J13 GND (power), K3 I4 (in), K4 VCC (power), K7 VCC (power), K8 GND (power), K9 GND (power), K10 VCC (power), K13 VCC (power), L4 GND (power), L13 GND (power), M4 VCC (power), M13 GND (power), N3 TCK (in), N4 GND (power), N5 GND (power), N6 VCC (power), N7 GND (power), N8 GND (power), N9 VCC (power), N10 GND (power), N11 VCC (power), N12 GND (power), N13 VCC (power), N14 ~{ENABLE} (in), P3 TMS (in), P7 I6 (in), R11 I7 (in), T7 I5 (in), T8 CLK1 (in), T11 CLK2 (in), T12 I8 (in)
part C pins: A7 NC, A8 NC, A9 NC, B1 NC, B7 NC, B8 NC, B9 NC, C8 NC, C9 NC, C14 NC, D16 NC, E5 NC, E7 NC, E8 NC, E15 NC, F7 NC, F8 NC, G12 NC, G16 NC, H1 NC, H2 NC, H3 NC, J1 NC, J2 NC, J3 NC, J5 NC, K2 NC, K5 NC, K6 NC, K11 NC, K12 NC, K14 NC, K15 NC, K16 NC, L5 NC, L6 NC, L9 NC, L10 NC, L11 NC, L15 NC, L16 NC, M5 NC, M9 NC, M10 NC, P8 NC, P9 NC, P10 NC, R8 NC, R9 NC, R10 NC, T9 NC, T10 NC

## M4A3-256/128-7YC
designator U?
High-Performance EE CMOS In-System Programmable Logic
footprint PQFP208_N (Shrink QFP, 208-Leads, Body 28x28mm, Pitch 0.5mm, IPC Medium Density)
footprint PQFP208_L (Shrink QFP, 208-Leads, Body 28x28mm, Pitch 0.5mm, IPC High Density)
footprint PQFP208_M (Shrink QFP, 208-Leads, Body 28x28mm, Pitch 0.5mm, IPC Low Density)
3D model M4A3-PQFP208 (208-Pin Plastic Quad Flat Pack (PQFP208))
part A pins: 3 I/O16 C7 (io), 4 I/O17 C6 (io), 5 I/O18 C5 (io), 6 I/O19 C4 (io), 7 I/O20 C3 (io), 8 I/O21 C2 (io), 9 I/O22 C1 (io), 10 I/O23 C0 (io), 13 I/O24 D7 (io), 14 I/O25 D6 (io), 15 I/O26 D5 (io), 16 I/O27 D4 (io), 17 I/O28 D3 (io), 18 I/O29 D2 (io), 19 I/O30 D1 (io), 20 I/O31 D0 (io), 32 I/O32 E0 (io), 33 I/O33 E1 (io), 34 I/O34 E2 (io), 35 I/O35 E3 (io), 36 I/O36 E4 (io), 37 I/O37 E5 (io), 38 I/O38 E6 (io), 39 I/O39 E7 (io), 42 I/O40 F0 (io), 43 I/O41 F1 (io), 44 I/O42 F2 (io), 45 I/O43 F3 (io), 46 I/O44 F4 (io), 47 I/O45 F5 (io), 48 I/O46 F6 (io), 49 I/O47 F7 (io), 54 I/O48 G7 (io), 55 I/O49 G6 (io), 56 I/O50 G5 (io), 57 I/O51 G4 (io), 58 I/O52 G3 (io), 59 I/O53 G2 (io), 60 I/O54 G1 (io), 61 I/O55 G0 (io), 64 I/O56 H7 (io), 65 I/O57 H6 (io), 66 I/O58 H5 (io), 67 I/O59 H4 (io), 68 I/O60 H3 (io), 69 I/O61 H2 (io), 70 I/O62 H1 (io), 71 I/O63 H0 (io), 190 I/O0 A0 (io), 191 I/O1 A1 (io), 192 I/O2 A2 (io), 193 I/O3 A3 (io), 194 I/O4 A4 (io), 195 I/O5 A5 (io), 196 I/O6 A6 (io), 197 I/O7 A7 (io), 200 I/O8 B0 (io), 201 I/O9 B1 (io), 202 I/O10 B2 (io), 203 I/O11 B3 (io), 204 I/O12 B4 (io), 205 I/O13 B5 (io), 206 I/O14 B6 (io), 207 I/O15 B7 (io)
part B pins: 86 I/O64 I0 (io), 87 I/O65 I1 (io), 88 I/O66 I2 (io), 89 I/O67 I3 (io), 90 I/O68 I4 (io), 91 I/O69 I5 (io), 92 I/O70 I6 (io), 93 I/O71 I7 (io), 96 I/O72 J0 (io), 97 I/O73 J1 (io), 98 I/O74 J2 (io), 99 I/O75 J3 (io), 100 I/O76 J4 (io), 101 I/O77 J5 (io), 102 I/O78 J6 (io), 103 I/O79 J7 (io), 107 I/O80 K7 (io), 108 I/O81 K6 (io), 109 I/O82 K5 (io), 110 I/O83 K4 (io), 111 I/O84 K3 (io), 112 I/O85 K2 (io), 113 I/O86 K1 (io), 114 I/O87 K0 (io), 117 I/O88 L7 (io), 118 I/O89 L6 (io), 119 I/O90 L5 (io), 120 I/O91 L4 (io), 121 I/O92 L3 (io), 122 I/O93 L2 (io), 123 I/O94 L1 (io), 124 I/O95 L0 (io), 136 I/O96 M0 (io), 137 I/O97 M1 (io), 138 I/O98 M2 (io), 139 I/O99 M3 (io), 140 I/O100 M4 (io), 141 I/O101 M5 (io), 142 I/O102 M6 (io), 143 I/O103 M7 (io), 146 I/O104 N0 (io), 147 I/O105 N1 (io), 148 I/O106 N2 (io), 149 I/O107 N3 (io), 150 I/O108 N4 (io), 151 I/O109 N5 (io), 152 I/O110 N6 (io), 153 I/O111 N7 (io), 158 I/O112 O7 (io), 159 I/O113 O6 (io), 160 I/O114 O5 (io), 161 I/O115 O4 (io), 162 I/O116 O3 (io), 163 I/O117 O2 (io), 164 I/O118 O1 (io), 165 I/O119 O0 (io), 168 I/O120 P7 (io), 169 I/O121 P6 (io), 170 I/O122 P5 (io), 171 I/O123 P4 (io), 172 I/O124 P3 (io), 173 I/O125 P2 (io), 174 I/O126 P1 (io), 175 I/O127 P0 (io)
part C pins: 1 GND (power), 2 TDI (in), 11 VCC (power), 12 GND (power), 21 I2 (in), 22 I3 (in), 23 GND (power), 24 VCC (power), 25 VCC (power), 26 GND (power), 27 GND (power), 28 VCC (power), 29 VCC (power), 30 GND (power), 31 I4 (in), 40 GND (power), 41 VCC (power), 50 TMS (in), 51 TCK (in), 52 GND (power), 53 GND (power), 62 GND (power), 63 VCC (power), 72 I5 (in), 73 I6 (in), 74 CLK1 (in), 75 VCC (power), 76 GND (power), 77 GND (power), 78 VCC (power), 79 VCC (power), 80 GND (power), 81 GND (power), 82 VCC (power), 83 CLK2 (in), 84 I7 (in), 85 I8 (in), 94 VCC (power), 95 GND (power), 104 GND (power), 105 GND (power), 106 ~{ENABLE} (in), 115 VCC (power), 116 GND (power), 125 I9 (in), 126 I10 (in), 127 GND (power), 128 VCC (power), 129 VCC (power), 130 GND (power), 131 GND (power), 132 VCC (power), 133 VCC (power), 134 GND (power), 135 I11 (in), 144 GND (power), 145 VCC (power), 154 ~{TRST} (in), 155 TDO (out), 156 GND (power), 157 GND (power), 166 GND (power), 167 VCC (power), 176 I12 (in), 177 I13 (in), 178 CLK3 (in), 179 VCC (power), 180 GND (power), 181 GND (power), 182 VCC (power), 183 VCC (power), 184 GND (power), 185 GND (power), 186 VCC (power), 187 CLK0 (in), 188 I0 (in), 189 I1 (in), 198 VCC (power), 199 GND (power), 208 GND (power)

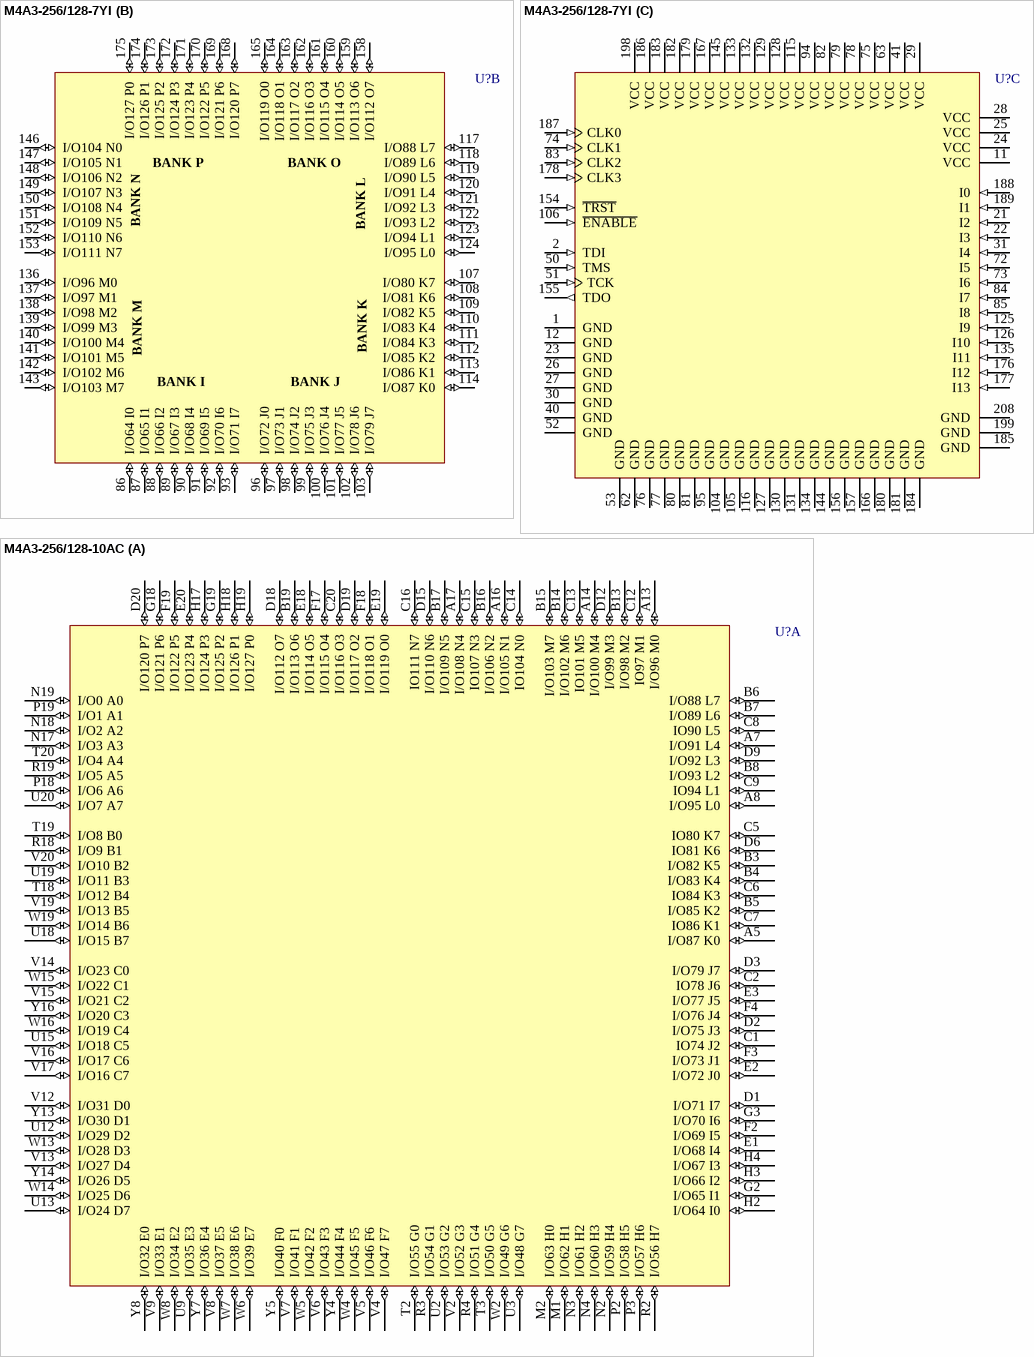
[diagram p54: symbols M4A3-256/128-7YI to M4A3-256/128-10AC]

## M4A3-256/128-7YI
designator U?
High-Performance EE CMOS In-System Programmable Logic
footprint PQFP208_N (Shrink QFP, 208-Leads, Body 28x28mm, Pitch 0.5mm, IPC Medium Density)
footprint PQFP208_L (Shrink QFP, 208-Leads, Body 28x28mm, Pitch 0.5mm, IPC High Density)
footprint PQFP208_M (Shrink QFP, 208-Leads, Body 28x28mm, Pitch 0.5mm, IPC Low Density)
3D model M4A3-PQFP208 (208-Pin Plastic Quad Flat Pack (PQFP208))
part A pins: 3 I/O16 C7 (io), 4 I/O17 C6 (io), 5 I/O18 C5 (io), 6 I/O19 C4 (io), 7 I/O20 C3 (io), 8 I/O21 C2 (io), 9 I/O22 C1 (io), 10 I/O23 C0 (io), 13 I/O24 D7 (io), 14 I/O25 D6 (io), 15 I/O26 D5 (io), 16 I/O27 D4 (io), 17 I/O28 D3 (io), 18 I/O29 D2 (io), 19 I/O30 D1 (io), 20 I/O31 D0 (io), 32 I/O32 E0 (io), 33 I/O33 E1 (io), 34 I/O34 E2 (io), 35 I/O35 E3 (io), 36 I/O36 E4 (io), 37 I/O37 E5 (io), 38 I/O38 E6 (io), 39 I/O39 E7 (io), 42 I/O40 F0 (io), 43 I/O41 F1 (io), 44 I/O42 F2 (io), 45 I/O43 F3 (io), 46 I/O44 F4 (io), 47 I/O45 F5 (io), 48 I/O46 F6 (io), 49 I/O47 F7 (io), 54 I/O48 G7 (io), 55 I/O49 G6 (io), 56 I/O50 G5 (io), 57 I/O51 G4 (io), 58 I/O52 G3 (io), 59 I/O53 G2 (io), 60 I/O54 G1 (io), 61 I/O55 G0 (io), 64 I/O56 H7 (io), 65 I/O57 H6 (io), 66 I/O58 H5 (io), 67 I/O59 H4 (io), 68 I/O60 H3 (io), 69 I/O61 H2 (io), 70 I/O62 H1 (io), 71 I/O63 H0 (io), 190 I/O0 A0 (io), 191 I/O1 A1 (io), 192 I/O2 A2 (io), 193 I/O3 A3 (io), 194 I/O4 A4 (io), 195 I/O5 A5 (io), 196 I/O6 A6 (io), 197 I/O7 A7 (io), 200 I/O8 B0 (io), 201 I/O9 B1 (io), 202 I/O10 B2 (io), 203 I/O11 B3 (io), 204 I/O12 B4 (io), 205 I/O13 B5 (io), 206 I/O14 B6 (io), 207 I/O15 B7 (io)
part B pins: 86 I/O64 I0 (io), 87 I/O65 I1 (io), 88 I/O66 I2 (io), 89 I/O67 I3 (io), 90 I/O68 I4 (io), 91 I/O69 I5 (io), 92 I/O70 I6 (io), 93 I/O71 I7 (io), 96 I/O72 J0 (io), 97 I/O73 J1 (io), 98 I/O74 J2 (io), 99 I/O75 J3 (io), 100 I/O76 J4 (io), 101 I/O77 J5 (io), 102 I/O78 J6 (io), 103 I/O79 J7 (io), 107 I/O80 K7 (io), 108 I/O81 K6 (io), 109 I/O82 K5 (io), 110 I/O83 K4 (io), 111 I/O84 K3 (io), 112 I/O85 K2 (io), 113 I/O86 K1 (io), 114 I/O87 K0 (io), 117 I/O88 L7 (io), 118 I/O89 L6 (io), 119 I/O90 L5 (io), 120 I/O91 L4 (io), 121 I/O92 L3 (io), 122 I/O93 L2 (io), 123 I/O94 L1 (io), 124 I/O95 L0 (io), 136 I/O96 M0 (io), 137 I/O97 M1 (io), 138 I/O98 M2 (io), 139 I/O99 M3 (io), 140 I/O100 M4 (io), 141 I/O101 M5 (io), 142 I/O102 M6 (io), 143 I/O103 M7 (io), 146 I/O104 N0 (io), 147 I/O105 N1 (io), 148 I/O106 N2 (io), 149 I/O107 N3 (io), 150 I/O108 N4 (io), 151 I/O109 N5 (io), 152 I/O110 N6 (io), 153 I/O111 N7 (io), 158 I/O112 O7 (io), 159 I/O113 O6 (io), 160 I/O114 O5 (io), 161 I/O115 O4 (io), 162 I/O116 O3 (io), 163 I/O117 O2 (io), 164 I/O118 O1 (io), 165 I/O119 O0 (io), 168 I/O120 P7 (io), 169 I/O121 P6 (io), 170 I/O122 P5 (io), 171 I/O123 P4 (io), 172 I/O124 P3 (io), 173 I/O125 P2 (io), 174 I/O126 P1 (io), 175 I/O127 P0 (io)
part C pins: 1 GND (power), 2 TDI (in), 11 VCC (power), 12 GND (power), 21 I2 (in), 22 I3 (in), 23 GND (power), 24 VCC (power), 25 VCC (power), 26 GND (power), 27 GND (power), 28 VCC (power), 29 VCC (power), 30 GND (power), 31 I4 (in), 40 GND (power), 41 VCC (power), 50 TMS (in), 51 TCK (in), 52 GND (power), 53 GND (power), 62 GND (power), 63 VCC (power), 72 I5 (in), 73 I6 (in), 74 CLK1 (in), 75 VCC (power), 76 GND (power), 77 GND (power), 78 VCC (power), 79 VCC (power), 80 GND (power), 81 GND (power), 82 VCC (power), 83 CLK2 (in), 84 I7 (in), 85 I8 (in), 94 VCC (power), 95 GND (power), 104 GND (power), 105 GND (power), 106 ~{ENABLE} (in), 115 VCC (power), 116 GND (power), 125 I9 (in), 126 I10 (in), 127 GND (power), 128 VCC (power), 129 VCC (power), 130 GND (power), 131 GND (power), 132 VCC (power), 133 VCC (power), 134 GND (power), 135 I11 (in), 144 GND (power), 145 VCC (power), 154 ~{TRST} (in), 155 TDO (out), 156 GND (power), 157 GND (power), 166 GND (power), 167 VCC (power), 176 I12 (in), 177 I13 (in), 178 CLK3 (in), 179 VCC (power), 180 GND (power), 181 GND (power), 182 VCC (power), 183 VCC (power), 184 GND (power), 185 GND (power), 186 VCC (power), 187 CLK0 (in), 188 I0 (in), 189 I1 (in), 198 VCC (power), 199 GND (power), 208 GND (power)

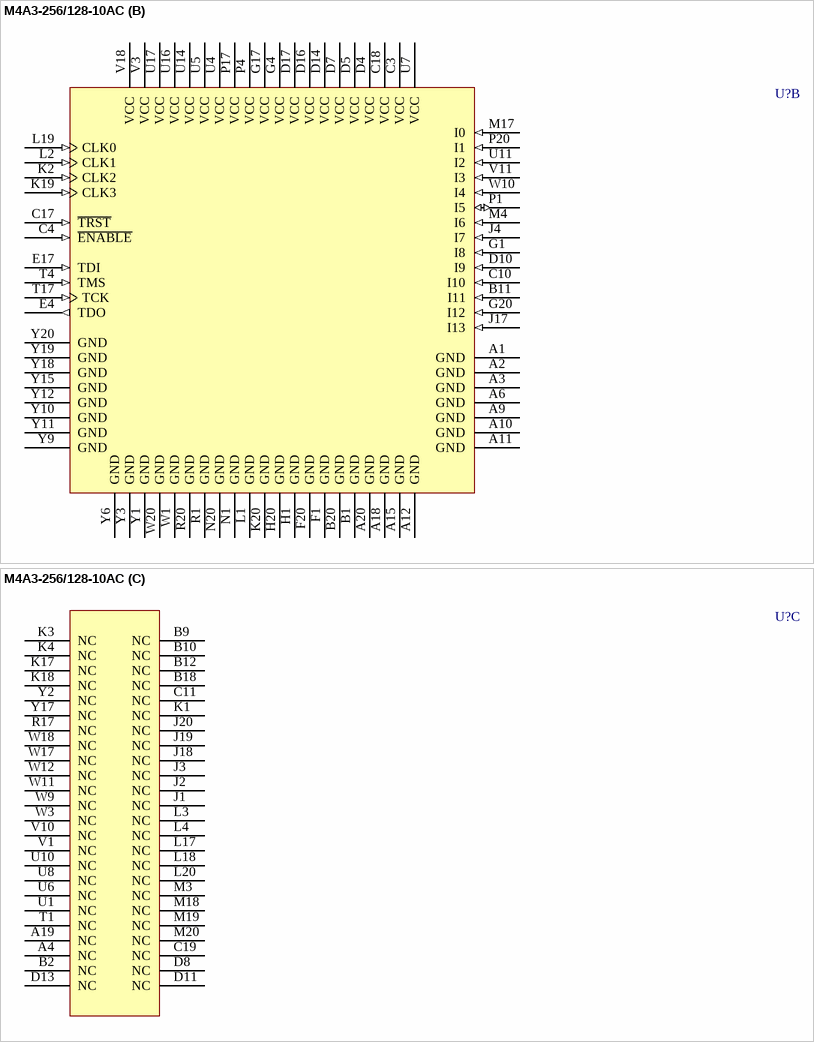
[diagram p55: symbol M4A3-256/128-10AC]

## M4A3-256/128-10AC
designator U?
High-Performance EE CMOS In-System Programmable Logic
footprint SBGA256 (BGA, 256-Leads, Body 27x27mm, Pitch 1.27mm)
3D model M4A3-SBGA256 (256-Ball Super Ball Grid Array (SBGA256))
part A pins: A5 I/O87 K0 (io), A7 I/O91 L4 (io), A8 I/O95 L0 (io), A13 I/O96 M0 (io), A14 I/O100 M4 (io), A16 I/O105 N1 (io), A17 I/O108 N4 (io), B3 I/O82 K5 (io), B4 I/O83 K4 (io), B5 I/O85 K2 (io), B6 I/O88 L7 (io), B7 I/O89 L6 (io), B8 I/O93 L2 (io), B13 I/O98 M2 (io), B14 I/O102 M6 (io), B15 I/O103 M7 (io), B16 I/O106 N2 (io), B17 I/O109 N5 (io), B19 I/O113 O6 (io), C1 IO74 J2 (io), C2 IO78 J6 (io), C5 IO80 K7 (io), C6 IO84 K3 (io), C7 IO86 K1 (io), C8 IO90 L5 (io), C9 IO94 L1 (io), C12 IO97 M1 (io), C13 IO101 M5 (io), C14 IO104 N0 (io), C15 IO107 N3 (io), C16 IO111 N7 (io), C20 I/O116 O3 (io), D1 I/O71 I7 (io), D2 I/O75 J3 (io), D3 I/O79 J7 (io), D6 IO81 K6 (io), D9 I/O92 L3 (io), D12 I/O99 M3 (io), D15 I/O110 N6 (io), D18 I/O112 O7 (io), D19 I/O117 O2 (io), D20 I/O120 P7 (io), E1 I/O68 I4 (io), E2 I/O72 J0 (io), E3 I/O77 J5 (io), E18 I/O114 O5 (io), E19 I/O119 O0 (io), E20 I/O123 P4 (io), F2 I/O69 I5 (io), F3 I/O73 J1 (io), F4 I/O76 J4 (io), F17 I/O115 O4 (io), F18 I/O118 O1 (io), F19 I/O122 P5 (io), G2 I/O65 I1 (io), G3 I/O70 I6 (io), G18 I/O121 P6 (io), G19 I/O125 P2 (io), H2 I/O64 I0 (io), H3 I/O66 I2 (io), H4 I/O67 I3 (io), H17 I/O124 P3 (io), H18 I/O126 P1 (io), H19 I/O127 P0 (io), M1 I/O62 H1 (io), M2 I/O63 H0 (io), N2 I/O59 H4 (io), N3 I/O61 H2 (io), N4 I/O60 H3 (io), N17 I/O3 A3 (io), N18 I/O2 A2 (io), N19 I/O0 A0 (io), P2 I/O58 H5 (io), P3 I/O57 H6 (io), P18 I/O6 A6 (io), P19 I/O1 A1 (io), R2 I/O56 H7 (io), R3 I/O54 G1 (io), R4 I/O51 G4 (io), R18 I/O9 B1 (io), R19 I/O5 A5 (io), T2 I/O55 G0 (io), T3 I/O50 G5 (io), T18 I/O12 B4 (io), T19 I/O8 B0 (io), T20 I/O4 A4 (io), U2 I/O53 G2 (io), U3 I/O48 G7 (io), U9 I/O35 E3 (io), U12 I/O29 D2 (io), U13 I/O24 D7 (io), U15 I/O18 C5 (io), U18 I/O15 B7 (io), U19 I/O11 B3 (io), U20 I/O7 A7 (io), V2 I/O52 G3 (io), V4 I/O47 F7 (io), V5 I/O46 F6 (io), V6 I/O43 F3 (io), V7 I/O41 F1 (io), V8 I/O37 E5 (io), V9 I/O33 E1 (io), V12 I/O31 D0 (io), V13 I/O27 D4 (io), V14 I/O23 C0 (io), V15 I/O21 C2 (io), V16 I/O17 C6 (io), V17 I/O16 C7 (io), V19 I/O13 B5 (io), V20 I/O10 B2 (io), W2 I/O49 G6 (io), W4 I/O45 F5 (io), W5 I/O42 F2 (io), W6 I/O39 E7 (io), W7 I/O38 E6 (io), W8 I/O34 E2 (io), W13 I/O28 D3 (io), W14 I/O25 D6 (io), W15 I/O22 C1 (io), W16 I/O19 C4 (io), W19 I/O14 B6 (io), Y4 I/O44 F4 (io), Y5 I/O40 F0 (io), Y7 I/O36 E4 (io), Y8 I/O32 E0 (io), Y13 I/O30 D1 (io), Y14 I/O26 D5 (io), Y16 I/O20 C3 (io)
part B pins: A1 GND (power), A2 GND (power), A3 GND (power), A6 GND (power), A9 GND (power), A10 GND (power), A11 GND (power), A12 GND (power), A15 GND (power), A18 GND (power), A20 GND (power), B1 GND (power), B11 I11 (in), B20 GND (power), C3 VCC (power), C4 ~{ENABLE} (in), C10 I10 (in), C17 ~{TRST} (in), C18 VCC (power), D4 VCC (power), D5 VCC (power), D7 VCC (power), D10 I9 (in), D14 VCC (power), D16 VCC (power), D17 VCC (power), E4 TDO (out), E17 TDI (in), F1 GND (power), F20 GND (power), G1 I8 (in), G4 VCC (power), G17 VCC (power), G20 I12 (in), H1 GND (power), H20 GND (power), J4 I7 (in), J17 I13 (in), K2 CLK2 (in), K19 CLK3 (in), K20 GND (power), L1 GND (power), L2 CLK1 (in), L19 CLK0 (in), M4 I6 (in), M17 I0 (in), N1 GND (power), N20 GND (power), P1 I5 (io), P4 VCC (power), P17 VCC (power), P20 I1 (in), R1 GND (power), R20 GND (power), T4 TMS (in), T17 TCK (in), U4 VCC (power), U5 VCC (power), U7 VCC (power), U11 I2 (in), U14 VCC (power), U16 VCC (power), U17 VCC (power), V3 VCC (power), V11 I3 (in), V18 VCC (power), W1 GND (power), W10 I4 (in), W20 GND (power), Y1 GND (power), Y3 GND (power), Y6 GND (power), Y9 GND (power), Y10 GND (power), Y11 GND (power), Y12 GND (power), Y15 GND (power), Y18 GND (power), Y19 GND (power), Y20 GND (power)
part C pins: A4 NC, A19 NC, B2 NC, B9 NC, B10 NC, B12 NC, B18 NC, C11 NC, C19 NC, D8 NC, D11 NC, D13 NC, J1 NC, J2 NC, J3 NC, J18 NC, J19 NC, J20 NC, K1 NC, K3 NC, K4 NC, K17 NC, K18 NC, L3 NC, L4 NC, L17 NC, L18 NC, L20 NC, M3 NC, M18 NC, M19 NC, M20 NC, R17 NC, T1 NC, U1 NC, U6 NC, U8 NC, U10 NC, V1 NC, V10 NC, W3 NC, W9 NC, W11 NC, W12 NC, W17 NC, W18 NC, Y2 NC, Y17 NC

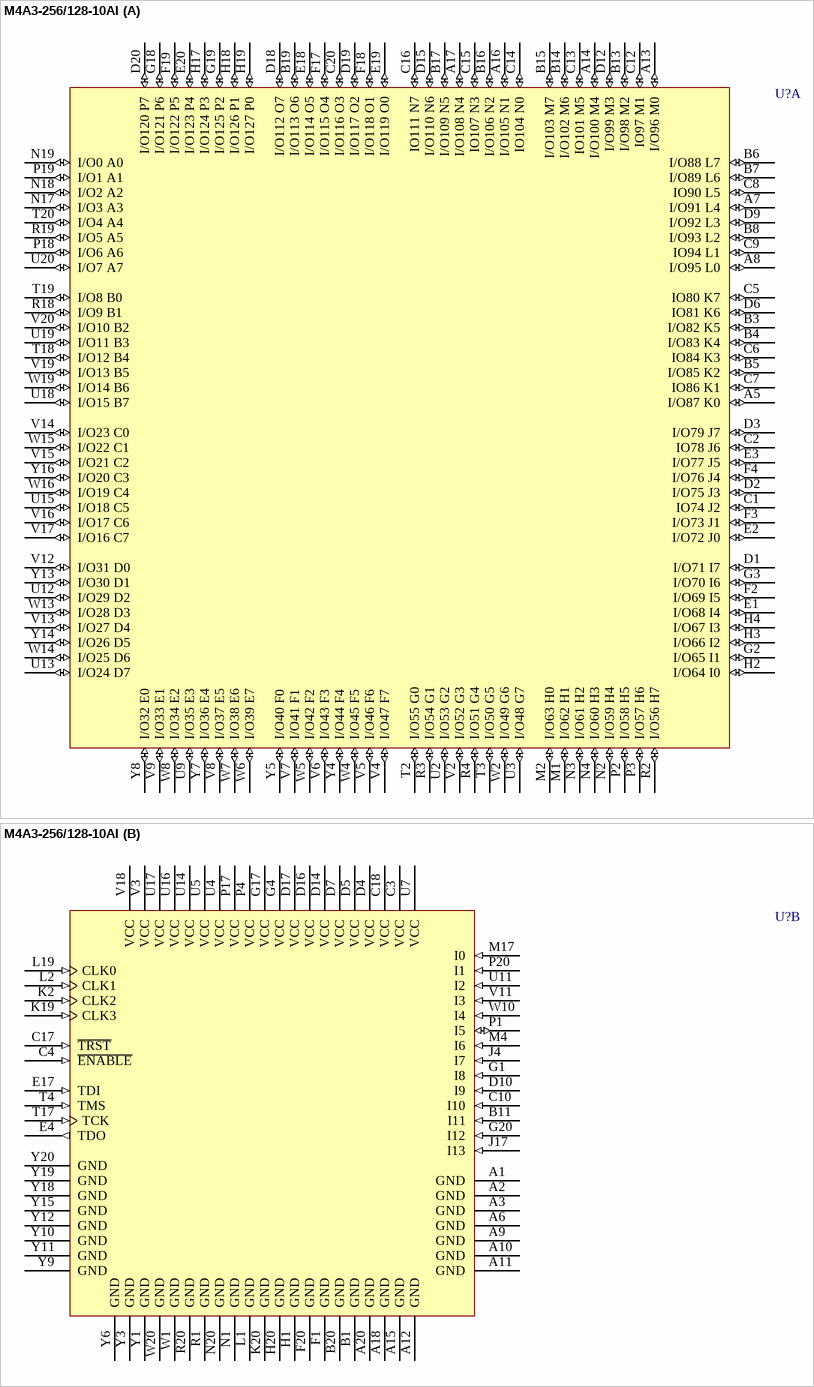
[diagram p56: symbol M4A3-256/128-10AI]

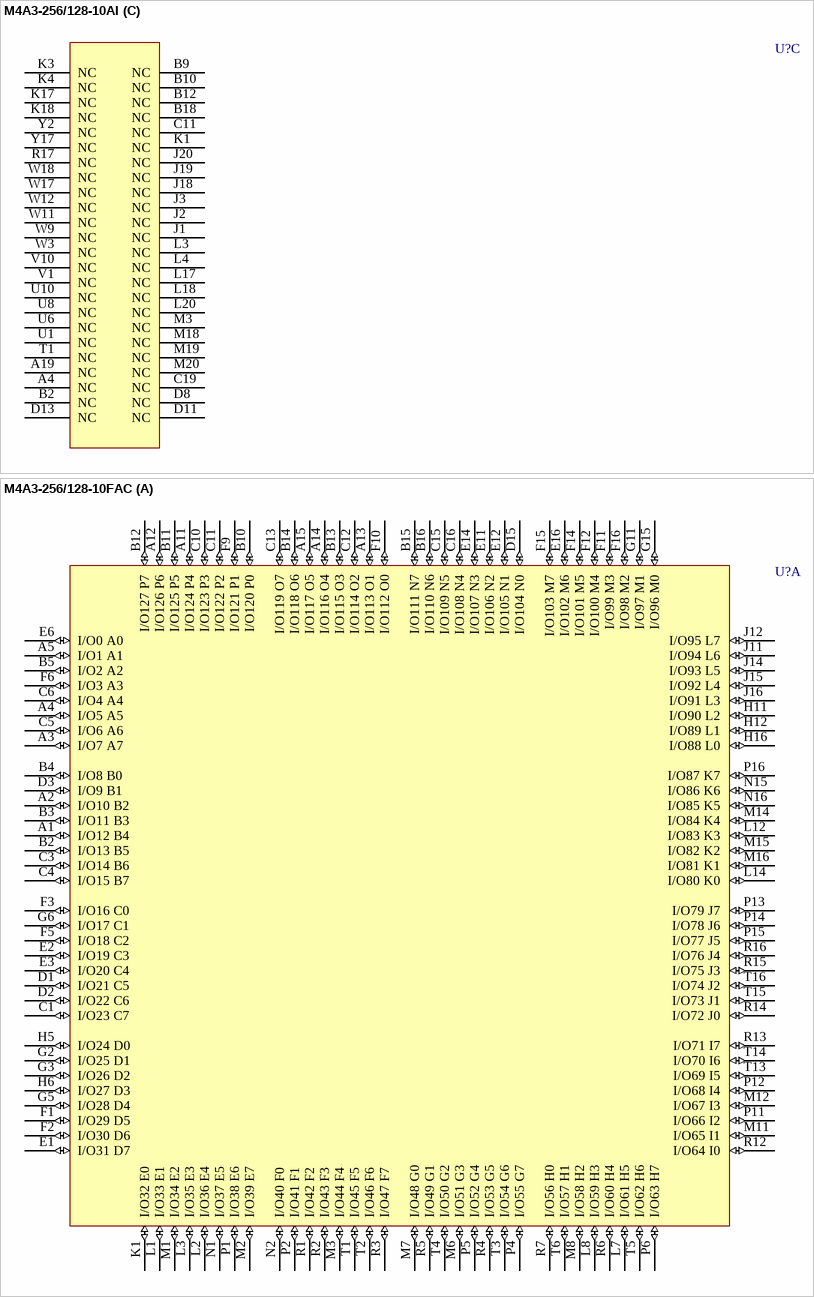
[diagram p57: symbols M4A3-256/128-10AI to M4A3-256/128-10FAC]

## M4A3-256/128-10AI
designator U?
High-Performance EE CMOS In-System Programmable Logic
footprint SBGA256 (BGA, 256-Leads, Body 27x27mm, Pitch 1.27mm)
3D model M4A3-SBGA256 (256-Ball Super Ball Grid Array (SBGA256))
part A pins: A5 I/O87 K0 (io), A7 I/O91 L4 (io), A8 I/O95 L0 (io), A13 I/O96 M0 (io), A14 I/O100 M4 (io), A16 I/O105 N1 (io), A17 I/O108 N4 (io), B3 I/O82 K5 (io), B4 I/O83 K4 (io), B5 I/O85 K2 (io), B6 I/O88 L7 (io), B7 I/O89 L6 (io), B8 I/O93 L2 (io), B13 I/O98 M2 (io), B14 I/O102 M6 (io), B15 I/O103 M7 (io), B16 I/O106 N2 (io), B17 I/O109 N5 (io), B19 I/O113 O6 (io), C1 IO74 J2 (io), C2 IO78 J6 (io), C5 IO80 K7 (io), C6 IO84 K3 (io), C7 IO86 K1 (io), C8 IO90 L5 (io), C9 IO94 L1 (io), C12 IO97 M1 (io), C13 IO101 M5 (io), C14 IO104 N0 (io), C15 IO107 N3 (io), C16 IO111 N7 (io), C20 I/O116 O3 (io), D1 I/O71 I7 (io), D2 I/O75 J3 (io), D3 I/O79 J7 (io), D6 IO81 K6 (io), D9 I/O92 L3 (io), D12 I/O99 M3 (io), D15 I/O110 N6 (io), D18 I/O112 O7 (io), D19 I/O117 O2 (io), D20 I/O120 P7 (io), E1 I/O68 I4 (io), E2 I/O72 J0 (io), E3 I/O77 J5 (io), E18 I/O114 O5 (io), E19 I/O119 O0 (io), E20 I/O123 P4 (io), F2 I/O69 I5 (io), F3 I/O73 J1 (io), F4 I/O76 J4 (io), F17 I/O115 O4 (io), F18 I/O118 O1 (io), F19 I/O122 P5 (io), G2 I/O65 I1 (io), G3 I/O70 I6 (io), G18 I/O121 P6 (io), G19 I/O125 P2 (io), H2 I/O64 I0 (io), H3 I/O66 I2 (io), H4 I/O67 I3 (io), H17 I/O124 P3 (io), H18 I/O126 P1 (io), H19 I/O127 P0 (io), M1 I/O62 H1 (io), M2 I/O63 H0 (io), N2 I/O59 H4 (io), N3 I/O61 H2 (io), N4 I/O60 H3 (io), N17 I/O3 A3 (io), N18 I/O2 A2 (io), N19 I/O0 A0 (io), P2 I/O58 H5 (io), P3 I/O57 H6 (io), P18 I/O6 A6 (io), P19 I/O1 A1 (io), R2 I/O56 H7 (io), R3 I/O54 G1 (io), R4 I/O51 G4 (io), R18 I/O9 B1 (io), R19 I/O5 A5 (io), T2 I/O55 G0 (io), T3 I/O50 G5 (io), T18 I/O12 B4 (io), T19 I/O8 B0 (io), T20 I/O4 A4 (io), U2 I/O53 G2 (io), U3 I/O48 G7 (io), U9 I/O35 E3 (io), U12 I/O29 D2 (io), U13 I/O24 D7 (io), U15 I/O18 C5 (io), U18 I/O15 B7 (io), U19 I/O11 B3 (io), U20 I/O7 A7 (io), V2 I/O52 G3 (io), V4 I/O47 F7 (io), V5 I/O46 F6 (io), V6 I/O43 F3 (io), V7 I/O41 F1 (io), V8 I/O37 E5 (io), V9 I/O33 E1 (io), V12 I/O31 D0 (io), V13 I/O27 D4 (io), V14 I/O23 C0 (io), V15 I/O21 C2 (io), V16 I/O17 C6 (io), V17 I/O16 C7 (io), V19 I/O13 B5 (io), V20 I/O10 B2 (io), W2 I/O49 G6 (io), W4 I/O45 F5 (io), W5 I/O42 F2 (io), W6 I/O39 E7 (io), W7 I/O38 E6 (io), W8 I/O34 E2 (io), W13 I/O28 D3 (io), W14 I/O25 D6 (io), W15 I/O22 C1 (io), W16 I/O19 C4 (io), W19 I/O14 B6 (io), Y4 I/O44 F4 (io), Y5 I/O40 F0 (io), Y7 I/O36 E4 (io), Y8 I/O32 E0 (io), Y13 I/O30 D1 (io), Y14 I/O26 D5 (io), Y16 I/O20 C3 (io)
part B pins: A1 GND (power), A2 GND (power), A3 GND (power), A6 GND (power), A9 GND (power), A10 GND (power), A11 GND (power), A12 GND (power), A15 GND (power), A18 GND (power), A20 GND (power), B1 GND (power), B11 I11 (in), B20 GND (power), C3 VCC (power), C4 ~{ENABLE} (in), C10 I10 (in), C17 ~{TRST} (in), C18 VCC (power), D4 VCC (power), D5 VCC (power), D7 VCC (power), D10 I9 (in), D14 VCC (power), D16 VCC (power), D17 VCC (power), E4 TDO (out), E17 TDI (in), F1 GND (power), F20 GND (power), G1 I8 (in), G4 VCC (power), G17 VCC (power), G20 I12 (in), H1 GND (power), H20 GND (power), J4 I7 (in), J17 I13 (in), K2 CLK2 (in), K19 CLK3 (in), K20 GND (power), L1 GND (power), L2 CLK1 (in), L19 CLK0 (in), M4 I6 (in), M17 I0 (in), N1 GND (power), N20 GND (power), P1 I5 (io), P4 VCC (power), P17 VCC (power), P20 I1 (in), R1 GND (power), R20 GND (power), T4 TMS (in), T17 TCK (in), U4 VCC (power), U5 VCC (power), U7 VCC (power), U11 I2 (in), U14 VCC (power), U16 VCC (power), U17 VCC (power), V3 VCC (power), V11 I3 (in), V18 VCC (power), W1 GND (power), W10 I4 (in), W20 GND (power), Y1 GND (power), Y3 GND (power), Y6 GND (power), Y9 GND (power), Y10 GND (power), Y11 GND (power), Y12 GND (power), Y15 GND (power), Y18 GND (power), Y19 GND (power), Y20 GND (power)
part C pins: A4 NC, A19 NC, B2 NC, B9 NC, B10 NC, B12 NC, B18 NC, C11 NC, C19 NC, D8 NC, D11 NC, D13 NC, J1 NC, J2 NC, J3 NC, J18 NC, J19 NC, J20 NC, K1 NC, K3 NC, K4 NC, K17 NC, K18 NC, L3 NC, L4 NC, L17 NC, L18 NC, L20 NC, M3 NC, M18 NC, M19 NC, M20 NC, R17 NC, T1 NC, U1 NC, U6 NC, U8 NC, U10 NC, V1 NC, V10 NC, W3 NC, W9 NC, W11 NC, W12 NC, W17 NC, W18 NC, Y2 NC, Y17 NC

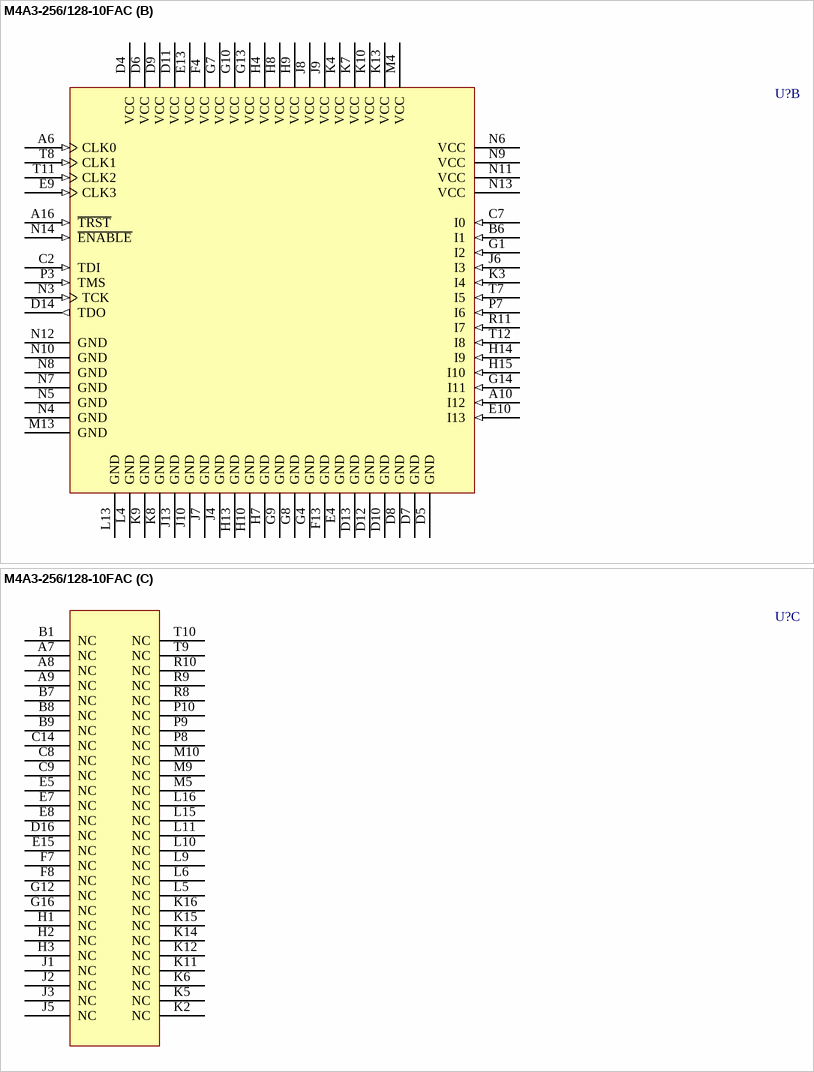
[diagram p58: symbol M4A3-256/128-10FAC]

## M4A3-256/128-10FAC
designator U?
High-Performance EE CMOS In-System Programmable Logic
footprint fpBGA256 (BGA, 256-Leads, Body 17x17mm, Pitch 1mm)
3D model M4A3-fpBGA256 (256-Ball Fine Pitch Ball Grid Array (fpBGA256))
part A pins: A1 I/O12 B4 (io), A2 I/O10 B2 (io), A3 I/O7 A7 (io), A4 I/O5 A5 (io), A5 I/O1 A1 (io), A11 I/O124 P4 (io), A12 I/O126 P6 (io), A13 I/O113 O1 (io), A14 I/O116 O4 (io), A15 I/O117 O5 (io), B2 I/O13 B5 (io), B3 I/O11 B3 (io), B4 I/O8 B0 (io), B5 I/O2 A2 (io), B10 I/O120 P0 (io), B11 I/O125 P5 (io), B12 I/O127 P7 (io), B13 I/O115 O3 (io), B14 I/O118 O6 (io), B15 I/O111 N7 (io), B16 I/O110 N6 (io), C1 I/O23 C7 (io), C3 I/O14 B6 (io), C4 I/O15 B7 (io), C5 I/O6 A6 (io), C6 I/O4 A4 (io), C10 I/O123 P3 (io), C11 I/O122 P2 (io), C12 I/O114 O2 (io), C13 I/O119 O7 (io), C15 I/O109 N5 (io), C16 I/O108 N4 (io), D1 I/O21 C5 (io), D2 I/O22 C6 (io), D3 I/O9 B1 (io), D15 I/O104 N0 (io), E1 I/O31 D7 (io), E2 I/O19 C3 (io), E3 I/O20 C4 (io), E6 I/O0 A0 (io), E11 I/O106 N2 (io), E12 I/O105 N1 (io), E14 I/O107 N3 (io), E16 I/O102 M6 (io), F1 I/O29 D5 (io), F2 I/O30 D6 (io), F3 I/O16 C0 (io), F5 I/O18 C2 (io), F6 I/O3 A3 (io), F9 I/O121 P1 (io), F10 I/O112 O0 (io), F11 I/O99 M3 (io), F12 I/O100 M4 (io), F14 I/O101 M5 (io), F15 I/O103 M7 (io), F16 I/O98 M2 (io), G2 I/O25 D1 (io), G3 I/O26 D2 (io), G5 I/O28 D4 (io), G6 I/O17 C1 (io), G11 I/O97 M1 (io), G15 I/O96 M0 (io), H5 I/O24 D0 (io), H6 I/O27 D3 (io), H11 I/O90 L2 (io), H12 I/O89 L1 (io), H16 I/O88 L0 (io), J11 I/O94 L6 (io), J12 I/O95 L7 (io), J14 I/O93 L5 (io), J15 I/O92 L4 (io), J16 I/O91 L3 (io), K1 I/O32 E0 (io), L1 I/O33 E1 (io), L2 I/O36 E4 (io), L3 I/O35 E3 (io), L7 I/O61 H5 (io), L8 I/O59 H3 (io), L12 I/O83 K3 (io), L14 I/O80 K0 (io), M1 I/O34 E2 (io), M2 I/O39 E7 (io), M3 I/O44 F4 (io), M6 I/O51 G3 (io), M7 I/O48 G0 (io), M8 I/O58 H2 (io), M11 I/O65 I1 (io), M12 I/O67 I3 (io), M14 I/O84 K4 (io), M15 I/O82 K2 (io), M16 I/O81 K1 (io), N1 I/O37 E5 (io), N2 I/O40 F0 (io), N15 I/O86 K6 (io), N16 I/O85 K5 (io), P1 I/O38 E6 (io), P2 I/O41 F1 (io), P4 I/O55 G7 (io), P5 I/O52 G4 (io), P6 I/O63 H7 (io), P11 I/O66 I2 (io), P12 I/O68 I4 (io), P13 I/O79 J7 (io), P14 I/O78 J6 (io), P15 I/O77 J5 (io), P16 I/O87 K7 (io), R1 I/O42 F2 (io), R2 I/O43 F3 (io), R3 I/O47 F7 (io), R4 I/O53 G5 (io), R5 I/O49 G1 (io), R6 I/O60 H4 (io), R7 I/O56 H0 (io), R12 I/O64 I0 (io), R13 I/O71 I7 (io), R14 I/O72 J0 (io), R15 I/O75 J3 (io), R16 I/O76 J4 (io), T1 I/O45 F5 (io), T2 I/O46 F6 (io), T3 I/O54 G6 (io), T4 I/O50 G2 (io), T5 I/O62 H6 (io), T6 I/O57 H1 (io), T13 I/O69 I5 (io), T14 I/O70 I6 (io), T15 I/O73 J1 (io), T16 I/O74 J2 (io)
part B pins: A6 CLK0 (in), A10 I12 (in), A16 ~{TRST} (in), B6 I1 (in), C2 TDI (in), C7 I0 (in), D4 VCC (power), D5 GND (power), D6 VCC (power), D7 GND (power), D8 GND (power), D9 VCC (power), D10 GND (power), D11 VCC (power), D12 GND (power), D13 GND (power), D14 TDO (out), E4 GND (power), E9 CLK3 (in), E10 I13 (in), E13 VCC (power), F4 VCC (power), F13 GND (power), G1 I2 (in), G4 GND (power), G7 VCC (power), G8 GND (power), G9 GND (power), G10 VCC (power), G13 VCC (power), G14 I11 (in), H4 VCC (power), H7 GND (power), H8 VCC (power), H9 VCC (power), H10 GND (power), H13 GND (power), H14 I9 (in), H15 I10 (in), J4 GND (power), J6 I3 (in), J7 GND (power), J8 VCC (power), J9 VCC (power), J10 GND (power), J13 GND (power), K3 I4 (in), K4 VCC (power), K7 VCC (power), K8 GND (power), K9 GND (power), K10 VCC (power), K13 VCC (power), L4 GND (power), L13 GND (power), M4 VCC (power), M13 GND (power), N3 TCK (in), N4 GND (power), N5 GND (power), N6 VCC (power), N7 GND (power), N8 GND (power), N9 VCC (power), N10 GND (power), N11 VCC (power), N12 GND (power), N13 VCC (power), N14 ~{ENABLE} (in), P3 TMS (in), P7 I6 (in), R11 I7 (in), T7 I5 (in), T8 CLK1 (in), T11 CLK2 (in), T12 I8 (in)
part C pins: A7 NC, A8 NC, A9 NC, B1 NC, B7 NC, B8 NC, B9 NC, C8 NC, C9 NC, C14 NC, D16 NC, E5 NC, E7 NC, E8 NC, E15 NC, F7 NC, F8 NC, G12 NC, G16 NC, H1 NC, H2 NC, H3 NC, J1 NC, J2 NC, J3 NC, J5 NC, K2 NC, K5 NC, K6 NC, K11 NC, K12 NC, K14 NC, K15 NC, K16 NC, L5 NC, L6 NC, L9 NC, L10 NC, L11 NC, L15 NC, L16 NC, M5 NC, M9 NC, M10 NC, P8 NC, P9 NC, P10 NC, R8 NC, R9 NC, R10 NC, T9 NC, T10 NC

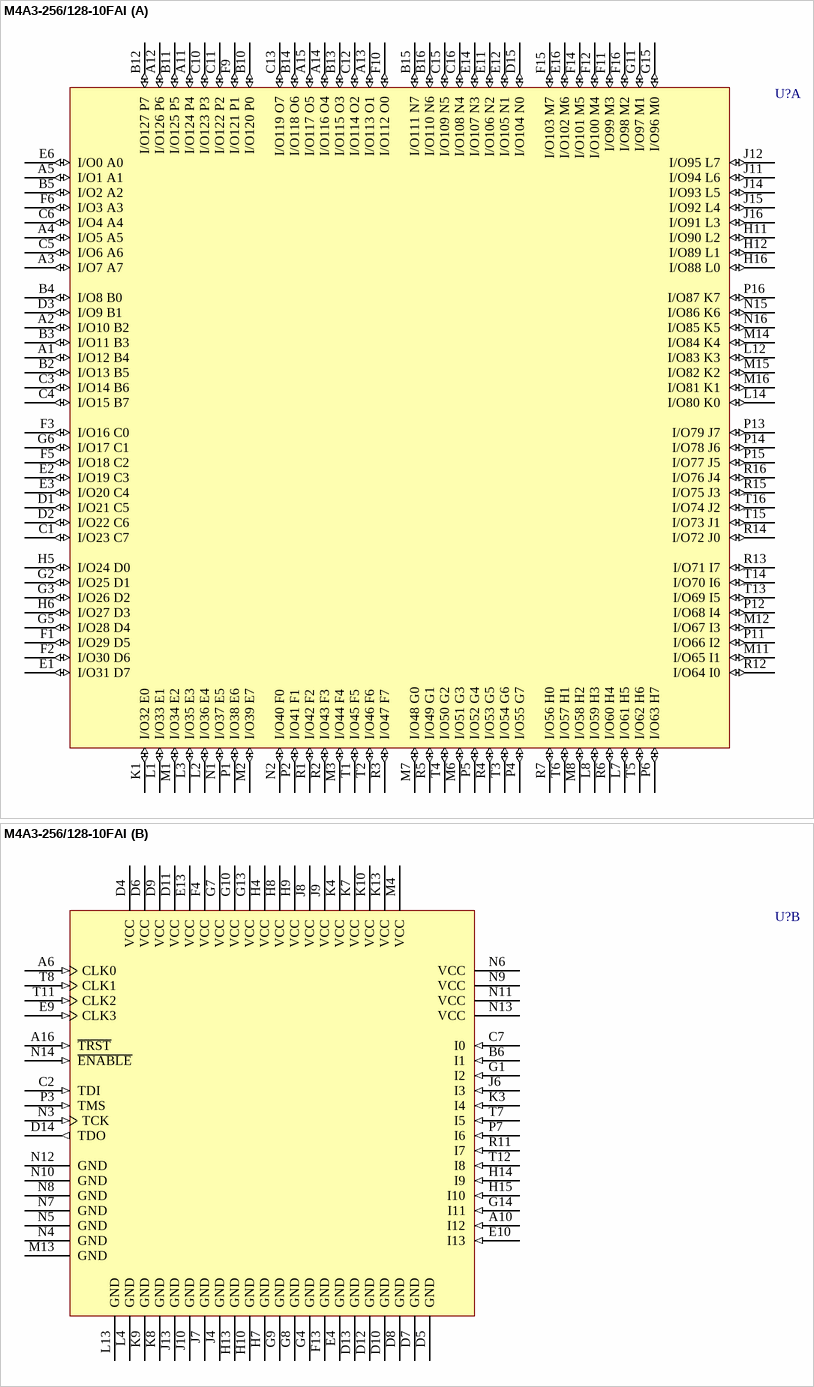
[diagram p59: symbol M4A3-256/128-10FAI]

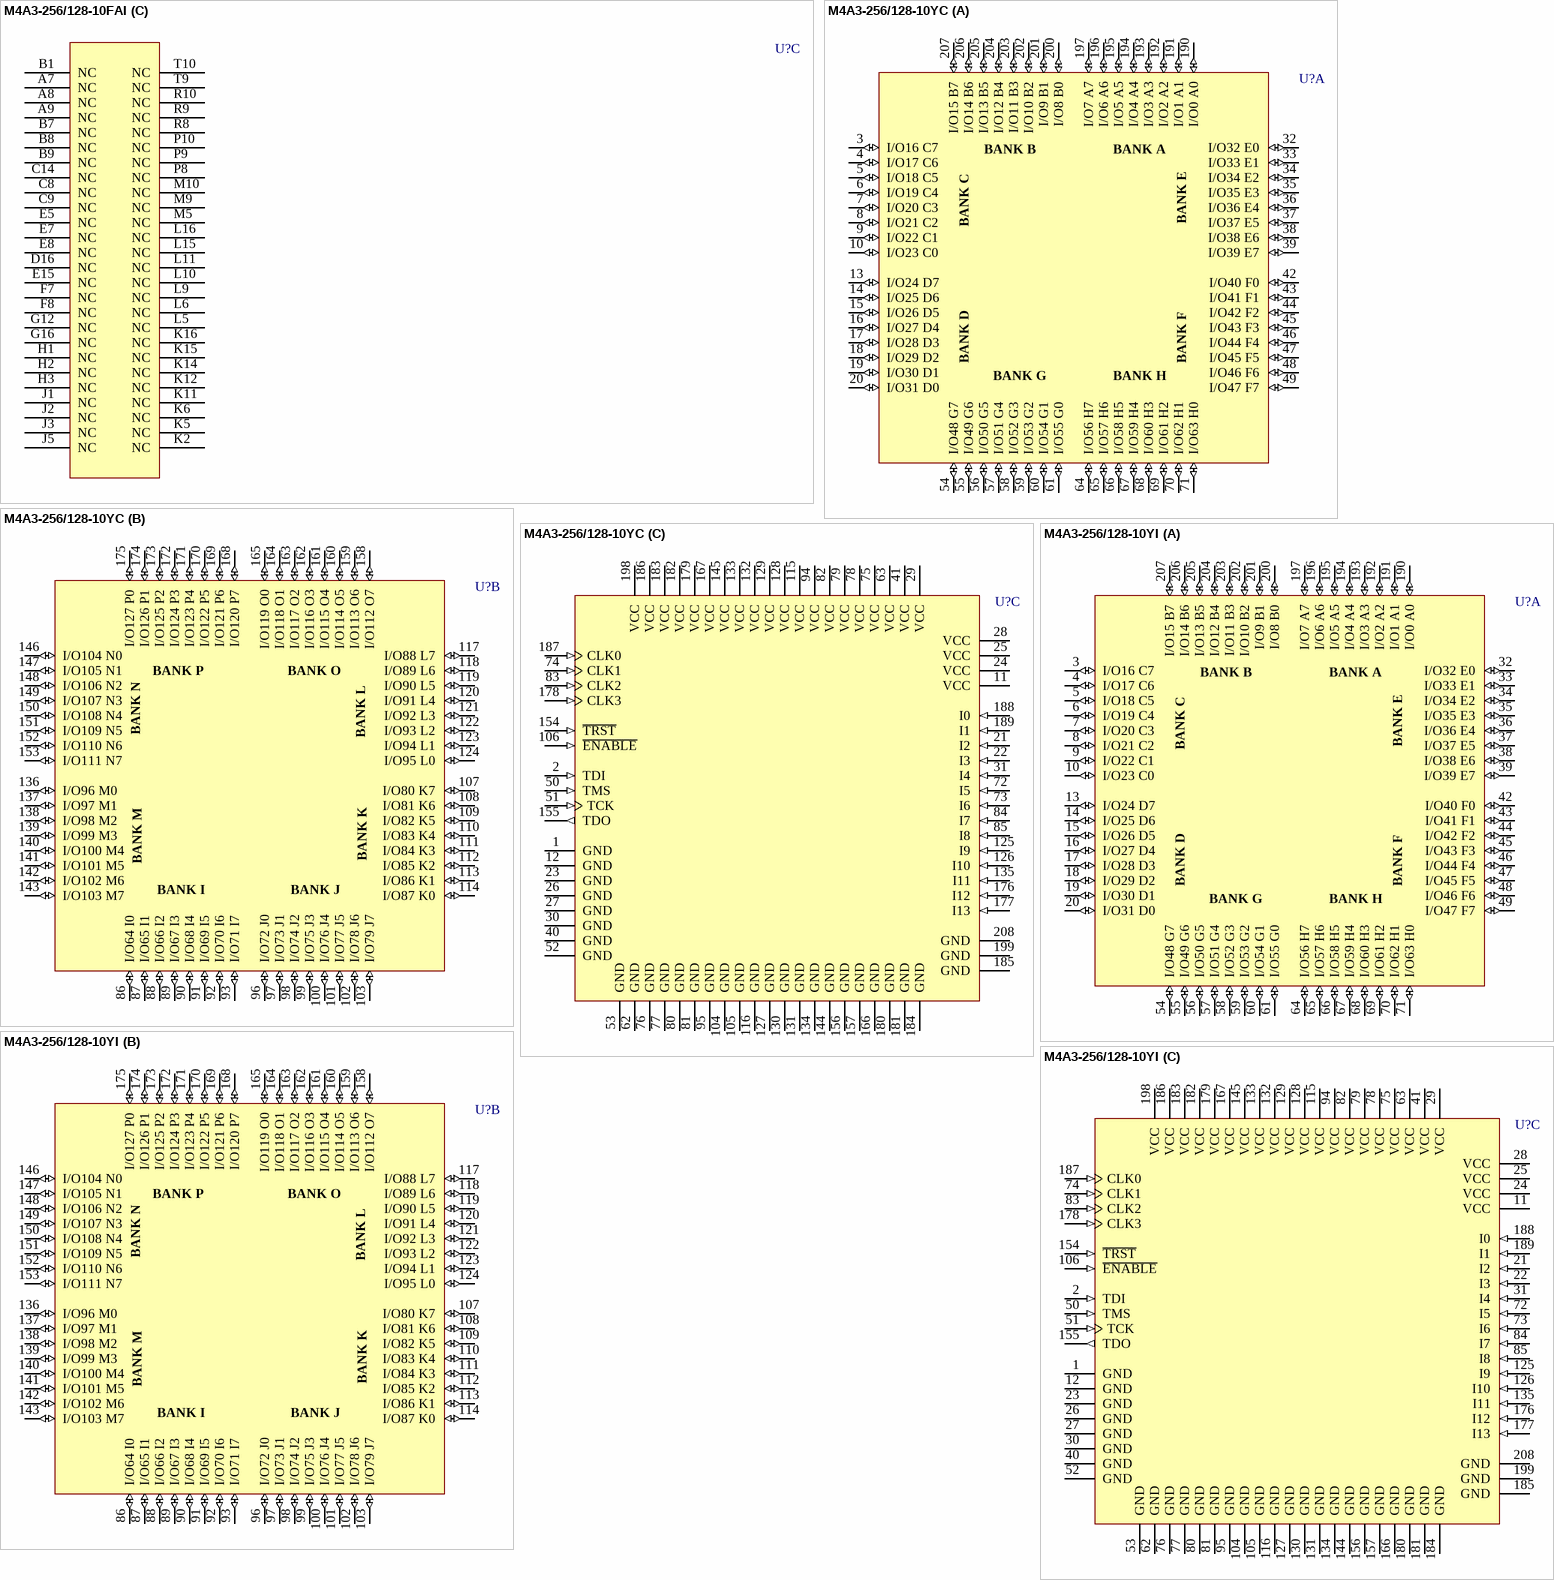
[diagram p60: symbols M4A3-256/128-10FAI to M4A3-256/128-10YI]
